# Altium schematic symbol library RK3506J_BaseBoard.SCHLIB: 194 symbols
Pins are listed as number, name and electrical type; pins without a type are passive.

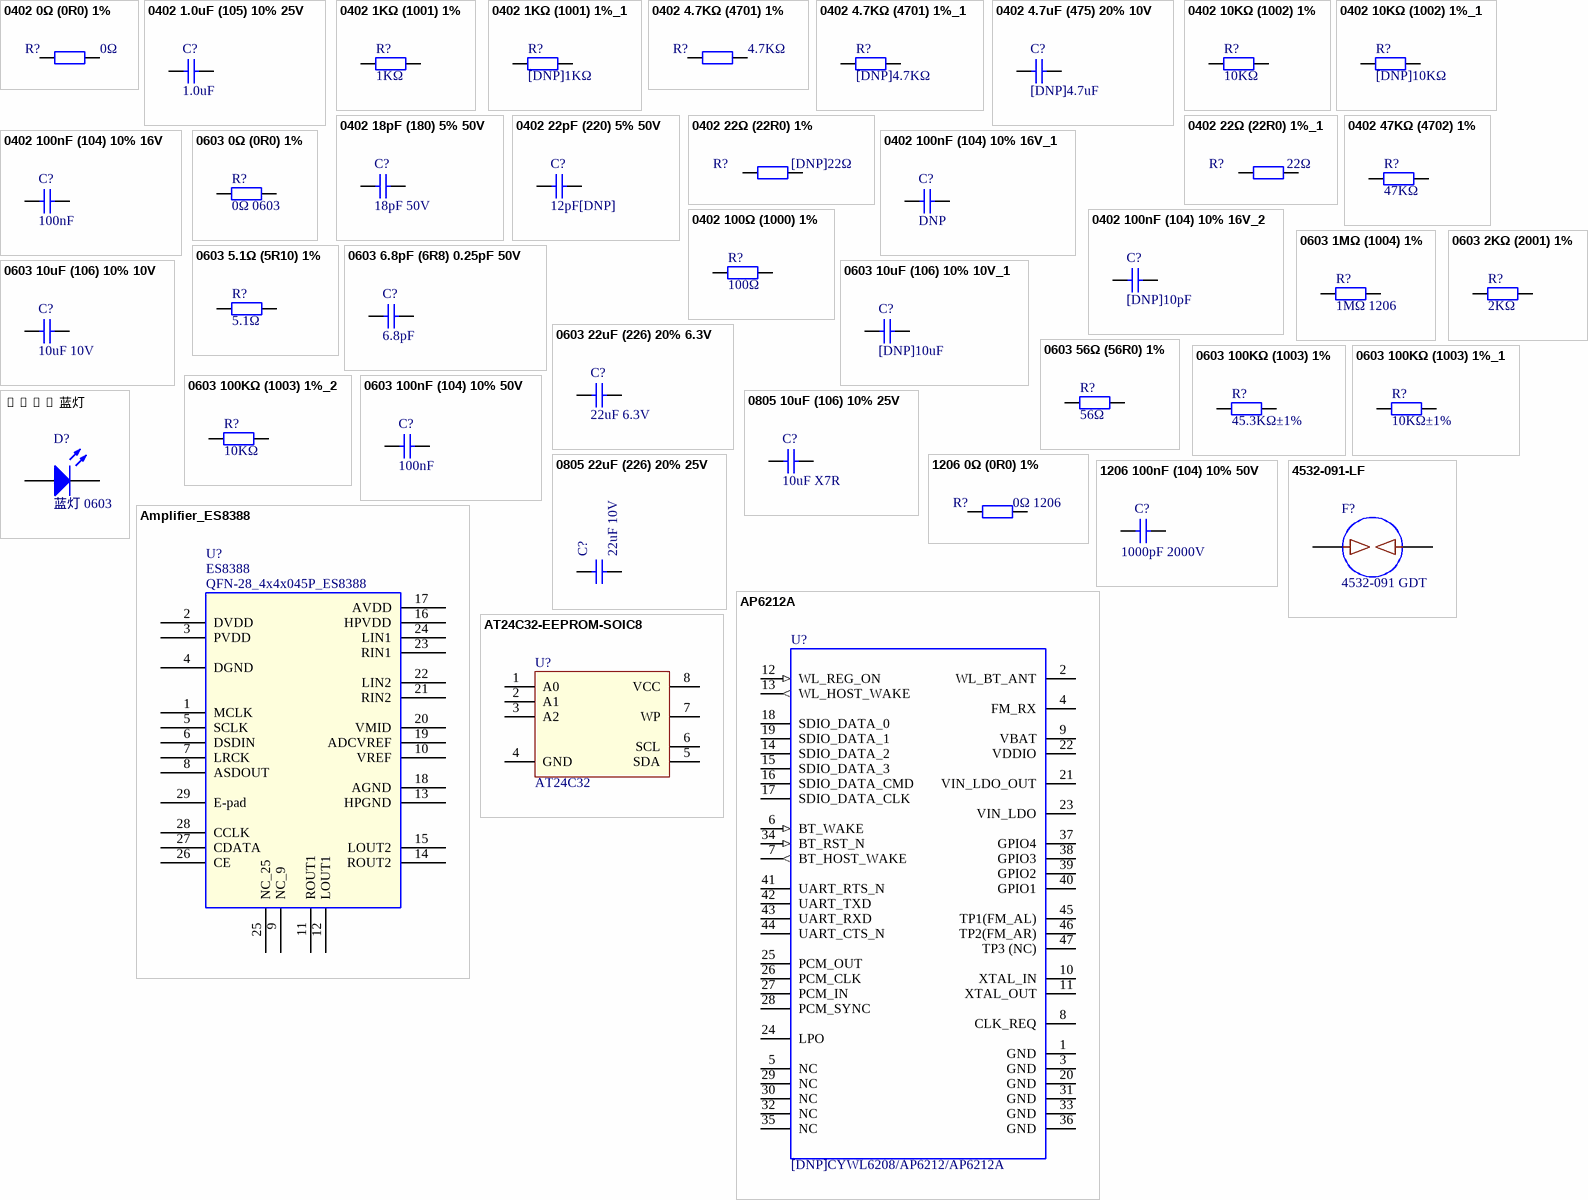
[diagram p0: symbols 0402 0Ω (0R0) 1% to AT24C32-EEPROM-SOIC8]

## 0402 0Ω (0R0) 1%
designator R?, comment 0Ω
贴片电阻
footprint 0402_R
pins: 1, 2

## 0402 1.0uF (105) 10% 25V
designator C?, comment 1.0uF
贴片电容
footprint 0402_C
pins: 1, 2

## 0402 1KΩ (1001) 1%
designator R?, comment 1KΩ
贴片电阻
footprint 0402_R
pins: 1, 2

## 0402 1KΩ (1001) 1%_1
designator R?, comment [DNP]1KΩ
贴片电阻
footprint 0402_R
pins: 1, 2

## 0402 4.7KΩ (4701) 1%
designator R?, comment 4.7KΩ
贴片电阻
footprint 0402_R
pins: 1, 2

## 0402 4.7KΩ (4701) 1%_1
designator R?, comment [DNP]4.7KΩ
贴片电阻
footprint 0402_R
pins: 1, 2

## 0402 4.7uF (475) 20% 10V
designator C?, comment [DNP]4.7uF
贴片电容
footprint 0402_C
pins: 1, 2

## 0402 10KΩ (1002) 1%
designator R?, comment 10KΩ
贴片电阻
footprint 0402_R
pins: 1, 2

## 0402 10KΩ (1002) 1%_1
designator R?, comment [DNP]10KΩ
贴片电阻
footprint 0402_R
pins: 1, 2

## 0402 18pF (180) 5% 50V
designator C?, comment 18pF 50V
贴片电容
footprint 0402_C
pins: 1, 2

## 0402 22pF (220) 5% 50V
designator C?, comment 12pF[DNP]
贴片电容
footprint 0402_C
pins: 1, 2

## 0402 22Ω (22R0) 1%
designator R?, comment [DNP]22Ω
贴片电阻
footprint SOLDER-BRIDGE_R0402-0R
pins: 1, 2

## 0402 22Ω (22R0) 1%_1
designator R?, comment 22Ω
贴片电阻
footprint SOLDER-BRIDGE_R0402-0R
pins: 1, 2

## 0402 47KΩ (4702) 1%
designator R?, comment 47KΩ
贴片电阻
footprint 0402_R
pins: 1, 2

## 0402 100nF (104) 10% 16V
designator C?, comment 100nF
贴片电容
footprint 0402_C
pins: 1, 2

## 0402 100nF (104) 10% 16V_1
designator C?, comment DNP
贴片电容
footprint 0402_C
pins: 1, 2

## 0402 100nF (104) 10% 16V_2
designator C?, comment [DNP]10pF
贴片电容
footprint 0402_C
pins: 1, 2

## 0402 100Ω (1000) 1%
designator R?, comment 100Ω
贴片电阻
footprint 0402_R
pins: 1, 2

## 0603 0Ω (0R0) 1%
designator R?, comment 0Ω 0603
贴片电阻
footprint SOLDER-BRIDGE_R0603-0R
pins: 1, 2

## 0603 1MΩ (1004) 1%
designator R?, comment 1MΩ 1206
贴片电阻
footprint 1206_R
pins: 1, 2

## 0603 2KΩ (2001) 1%
designator R?, comment 2KΩ
贴片电阻
footprint 0603_R
pins: 1, 2

## 0603 5.1Ω (5R10) 1%
designator R?, comment 5.1Ω
贴片电阻
footprint 0603_R
pins: 1, 2

## 0603 6.8pF (6R8) 0.25pF 50V
designator C?, comment 6.8pF
贴片电容
footprint 0603_C
pins: 1, 2

## 0603 10uF (106) 10% 10V
designator C?, comment 10uF 10V
贴片电容
footprint 0603_C
pins: 1, 2

## 0603 10uF (106) 10% 10V_1
designator C?, comment [DNP]10uF
贴片电容
footprint 0402_C
pins: 1, 2

## 0603 22uF (226) 20% 6.3V
designator C?, comment 22uF 6.3V
贴片电容
footprint 0603_C
pins: 1, 2

## 0603 56Ω (56R0) 1%
designator R?, comment 56Ω
贴片电阻
footprint 0603_R
pins: 1, 2

## 0603 100KΩ (1003) 1%
designator R?, comment 45.3KΩ±1%
贴片电阻
footprint 0603_R
pins: 1, 2

## 0603 100KΩ (1003) 1%_1
designator R?, comment 10KΩ±1%
贴片电阻
footprint 0603_R
pins: 1, 2

## 0603 100KΩ (1003) 1%_2
designator R?, comment 10KΩ
贴片电阻
footprint 0603_R
pins: 1, 2

## 0603 100nF (104) 10% 50V
designator C?, comment 100nF
贴片电容
footprint 0603_C
pins: 1, 2

## 0603 蓝灯
designator D?, comment 蓝灯 0603
发光二极管
footprint 0603_LED_S1
pins: A, K

## 0805 10uF (106) 10% 25V
designator C?, comment 10uF X7R
贴片电容
footprint 0805_C
pins: 1, 2

## 0805 22uF (226) 20% 25V
designator C?, comment 22uF 10V
贴片电容
footprint 0805_C
pins: 1, 2

## 1206 0Ω (0R0) 1%
designator R?, comment 0Ω 1206
贴片电阻
footprint 1206_R
pins: 1, 2

## 1206 100nF (104) 10% 50V
designator C?, comment 1000pF 2000V
贴片电容
footprint 1206_C
pins: 1, 2

## 4532-091-LF
designator F?, comment 4532-091 GDT
90V GDT, 1 pole
footprint D1812-BI
pins: 1, 2

## Amplifier_ES8388
designator U?, comment ES8388  PCB Footprint: QFN-28_4x4x045P_ES8388
ES8388 is a high performance, low power and low cost audio CODEC. It consists of 2-ch ADC, 2-ch DAC, microphone amplifier, headphone amplifier, digital sound effects, and analog mixing and gain functions.; Manufacturer: Everest（顺芯）
footprint QFN-28_4x4x045P_ES8388
pins: 1 MCLK, 2 DVDD, 3 PVDD, 4 DGND, 5 SCLK, 6 DSDIN, 7 LRCK, 8 ASDOUT, 9 NC_9, 10 VREF, 11 ROUT1, 12 LOUT1, 13 HPGND (power), 14 ROUT2, 15 LOUT2, 16 HPVDD, 17 AVDD, 18 AGND (power), 19 ADCVREF, 20 VMID, 21 RIN2, 22 LIN2, 23 RIN1, 24 LIN1, 25 NC_25, 26 CE, 27 CDATA, 28 CCLK, 29 E-pad

## AP6212A
designator U?, comment [DNP]CYWL6208/AP6212/AP6212A
footprint LGA44 (AP6212)
pins: 1 GND, 2 WL_BT_ANT, 3 GND, 4 FM_RX, 5 NC, 6 BT_WAKE (in), 7 BT_HOST_WAKE (out), 8 CLK_REQ, 9 VBAT, 10 XTAL_IN, 11 XTAL_OUT, 12 WL_REG_ON (in), 13 WL_HOST_WAKE (out), 14 SDIO_DATA_2, 15 SDIO_DATA_3, 16 SDIO_DATA_CMD, 17 SDIO_DATA_CLK, 18 SDIO_DATA_0, 19 SDIO_DATA_1, 20 GND, 21 VIN_LDO_OUT, 22 VDDIO, 23 VIN_LDO, 24 LPO, 25 PCM_OUT, 26 PCM_CLK, 27 PCM_IN, 28 PCM_SYNC, 29 NC, 30 NC, 31 GND, 32 NC, 33 GND, 34 BT_RST_N (in), 35 NC, 36 GND, 37 GPIO4, 38 GPIO3, 39 GPIO2, 40 GPIO1, 41 UART_RTS_N, 42 UART_TXD, 43 UART_RXD, 44 UART_CTS_N, 45 TP1(FM_AL), 46 TP2(FM_AR), 47 TP3 (NC)

## AT24C32-EEPROM-SOIC8
designator U?, comment AT24C32
AT24C32 EEPROM
footprint SOIC-8_150mil
pins: 1 A0, 2 A1, 3 A2, 4 GND, 5 SDA, 6 SCL, 7 WP, 8 VCC

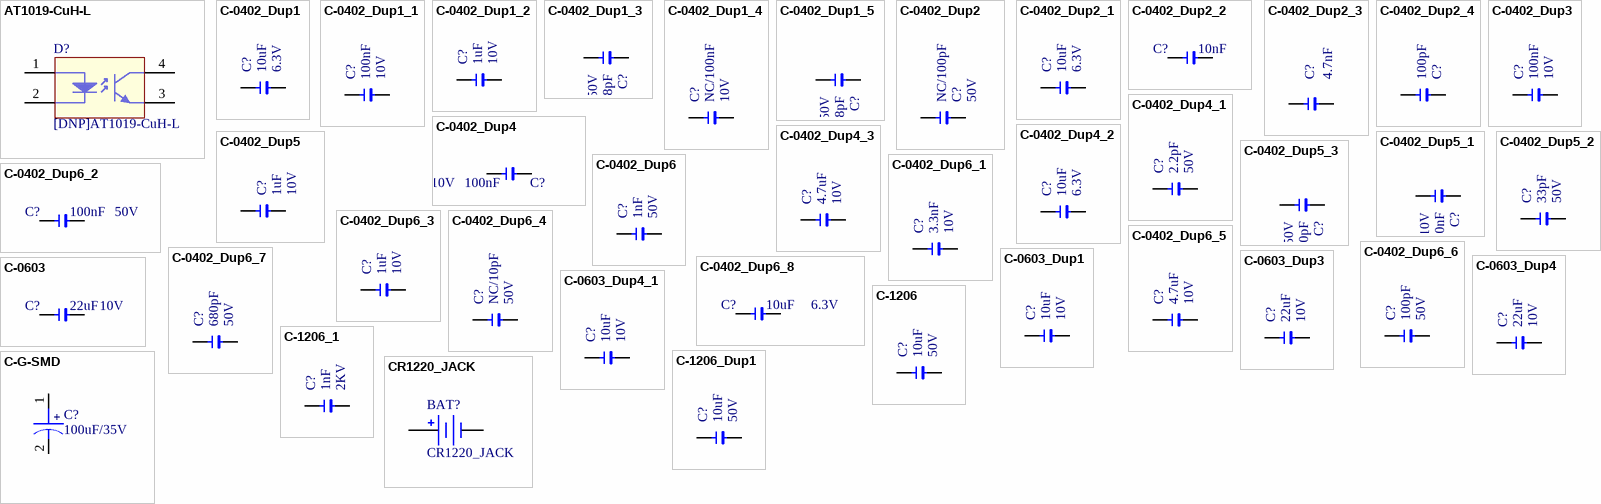
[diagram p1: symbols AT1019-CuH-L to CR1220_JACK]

## AT1019-CuH-L
designator D?, comment [DNP]AT1019-CuH-L
Photo Transistor，AT101X是一款由一个GaAs发光二极管和一个NPN光电晶体管组成的光电耦合器
footprint SOP4-300mil
pins: 1 A, 2 C, 3 E, 4 C

## C-0402_Dup1
designator C?, comment 10uF  DSC2: 6.3V
Part Number: C020102120068; Part Name: 贴片电容; PCB Footprint: C0402; DSC1: ±20%; DSC3: X5R; ID: 68
footprint C0402
pins: 1, 2

## C-0402_Dup1_1
designator C?, comment 100nF  DSC2: 10V
Part Number: C020102120060; Part Name: 贴片电容; PCB Footprint: C0402; ERP Number: 1010010034; DSC1: ±10%; DSC3: X7R; ID: 60
footprint C0402
pins: 1, 2

## C-0402_Dup1_2
designator C?, comment 1uF  DSC2: 10V
Part Name: 贴片电容; Part Number: C020102120064; PCB Footprint: C0402; ID: 64; DSC3: X5R; DSC1: ±10%; ERP Number: 1010010006
footprint C0402
pins: 1, 2

## C-0402_Dup1_3
designator C?, comment 18pF  DSC2: 50V
Part Number: C020102120027; Part Name: 贴片电容; PCB Footprint: C0402; ERP Number: 1010010007; DSC1: ±5%; DSC3: C0G; ID: 27
footprint C0402
pins: 1, 2

## C-0402_Dup1_4
designator C?, comment NC/100nF  DSC2: 10V
Part Number: C020102120060; Part Name: 贴片电容; ERP Number: 1010010034; DSC1: ±10%; DSC3: X7R; ID: 60; PCB Footprint: C0402
footprint C0402
pins: 1, 2

## C-0402_Dup1_5
designator C?, comment NC/18pF  DSC2: 50V
Part Number: C020102120027; Part Name: 贴片电容; PCB Footprint: C0402; ERP Number: 1010010007; DSC1: ±5%; DSC3: C0G; ID: 27
footprint C0402
pins: 1, 2

## C-0402_Dup2
designator C?, comment NC/100pF  DSC2: 50V
Part Number: C020102120040; Part Name: 贴片电容; ERP Number: 1010010013; DSC1: ±5%; DSC3: C0G; ID: 40; PCB Footprint: C0402
footprint C0402
pins: 1, 2

## C-0402_Dup2_1
designator C?, comment 10uF  DSC2: 6.3V
Part Name: 贴片电容; Part Number: C020102120068; PCB Footprint: C0402; ID: 68; DSC3: X5R; DSC1: ±20%
footprint C0402
pins: 1, 2

## C-0402_Dup2_2
designator C?, comment 10nF
Part Number: C020102120057; Part Name: 贴片电容; ERP Number: 1010010015; DSC1: ±10%; DSC2: 50V; DSC3: X7R; ID: 57; PCB Footprint: C0402
footprint C0402
pins: 1, 2

## C-0402_Dup2_3
designator C?, comment 4.7nF
Part Name: 贴片电容; Part Number: C020102120056; ID: 56; DSC3: X7R; DSC2: 50V; DSC1: ±10%; ERP Number: 1010010041; PCB Footprint: C0402
footprint C0402
pins: 1, 2

## C-0402_Dup2_4
designator C?, comment 100pF
Part Number: C020102120040; Part Name: 贴片电容; ERP Number: 1010010013; DSC1: ±5%; DSC2: 50V; DSC3: C0G; ID: 40; PCB Footprint: C0402
footprint C0402
pins: 1, 2

## C-0402_Dup3
designator C?, comment 100nF  DSC2: 10V
Manufacture: 三星¦国巨¦村田; Part Name: 贴片电容; Part Number: C020102120060; PCB Footprint: C0402; ID: 60; DSC3: X7R; DSC1: ±10%
footprint 1206
footprint C0402
pins: 1, 2

## C-0402_Dup4
designator C?, comment 100nF  DSC2: 10V
Manufacture: 三星¦国巨¦村田; Part Name: 贴片电容; Part Number: C020102120061; PCB Footprint: C0402; ID: 61; DSC3: X7R; DSC1: ±10%; ERP Number: 1010200128
footprint 1206
footprint C0402
pins: 1, 2

## C-0402_Dup4_1
designator C?, comment 2.2pF  DSC2: 50V
Part Number: C020102120013; Part Name: 贴片电容; Manufacture: 三星¦国巨¦村田; PCB Footprint: C0402; ERP Number: 1010200109; DSC1: ±0.1PF; DSC3: C0G; ID: 13
footprint 1206
footprint C0402
pins: 1, 2

## C-0402_Dup4_2
designator C?, comment 10uF  DSC2: 6.3V
Part Number: C020102120068; Part Name: 贴片电容; Manufacture: 三星¦国巨¦村田; PCB Footprint: C0402; DSC1: ±20%; DSC3: X5R; ID: 68
footprint 1206
footprint C0402
pins: 1, 2

## C-0402_Dup4_3
designator C?, comment 4.7uF  DSC2: 10V
Part Number: C020102120067; Part Name: 贴片电容; Manufacture: 三星¦国巨¦村田; PCB Footprint: C0402; DSC1: ±20%; DSC3: X5R; ID: 67
footprint 1206
footprint C0402
pins: 1, 2

## C-0402_Dup5
designator C?, comment 1uF  DSC2: 10V
Part Number: C020102120064; Part Name: 贴片电容; Manufacture: 三星¦国巨¦村田; ERP Number: 1010200054; DSC1: ±10%; DSC3: X5R; ID: 64; PCB Footprint: C0402
footprint 1206
footprint C0402
pins: 1, 2

## C-0402_Dup5_1
designator C?, comment 100nF  DSC2: 10V
Part Number: C020102120060; Part Name: 贴片电容; Manufacture: 三星¦国巨¦村田; DSC1: ±10%; DSC3: X7R; ID: 60; PCB Footprint: C0402
footprint 1206
footprint C0402
pins: 1, 2

## C-0402_Dup5_2
designator C?, comment 33pF  DSC2: 50V
Manufacture: 三星¦国巨¦村田; Part Name: 贴片电容; Part Number: C020102120033; ID: 33; DSC3: C0G; DSC1: ±5%; ERP Number: 1010200087; PCB Footprint: C0402
footprint 1206
footprint C0402
pins: 1, 2

## C-0402_Dup5_3
designator C?, comment 100pF  DSC2: 50V
Manufacture: 三星¦国巨¦村田; Part Name: 贴片电容; Part Number: C020102120040; ID: 40; DSC3: C0G; DSC1: ±5%; ERP Number: 1010200152; PCB Footprint: C0402
footprint 1206
footprint C0402
pins: 1, 2

## C-0402_Dup6
designator C?, comment 1nF  DSC2: 50V
Part Number: C020102120054; Part Name: 贴片电容; ERP Number: 1010010021; DSC1: ±10%; DSC3: X7R; ID: 54; PCB Footprint: C0402
footprint C0402
pins: 1, 2

## C-0402_Dup6_1
designator C?, comment 3.3nF  DSC2: 10V
Part Number: C020102120064; Part Name: 贴片电容; ERP Number: 1010010006; DSC1: ±10%; DSC3: X5R; ID: 64; PCB Footprint: C0402
footprint C0402
pins: 1, 2

## C-0402_Dup6_2
designator C?, comment 100nF  DSC2: 50V
Part Name: 贴片电容; Part Number: C020102120061; ID: 61; DSC3: X7R; DSC1: ±10%; PCB Footprint: C0402
footprint C0402
pins: 1, 2

## C-0402_Dup6_3
designator C?, comment 1uF  DSC2: 10V
Part Number: C020102120064; Part Name: 贴片电容; ERP Number: 1010010006; DSC1: ±10%; DSC3: X5R; ID: 64; PCB Footprint: C0402
footprint C0402
pins: 1, 2

## C-0402_Dup6_4
designator C?, comment NC/10pF  DSC2: 50V
Part Number: C020102120021; Part Name: 贴片电容; ERP Number: 1010010024; DSC1: ±5%; DSC3: C0G; ID: 21; PCB Footprint: C0402
footprint C0402
pins: 1, 2

## C-0402_Dup6_5
designator C?, comment 4.7uF  DSC2: 10V
Part Name: 贴片电容; Part Number: C020102120067; PCB Footprint: C0402; ID: 67; DSC3: X5R; DSC1: ±10%; ERP Number: 1010010043
footprint C0402
pins: 1, 2

## C-0402_Dup6_6
designator C?, comment 100pF  DSC2: 50V
Part Name: 贴片电容; Part Number: C020102120040; ID: 40; DSC3: C0G; DSC1: ±5%; ERP Number: 1010010013; PCB Footprint: C0402
footprint C0402
pins: 1, 2

## C-0402_Dup6_7
designator C?, comment 680pF  DSC2: 50V
Part Name: 贴片电容; Part Number: C020102120052; ID: 52; DSC3: C0G; DSC1: ±5%; ERP Number: 1010010039; PCB Footprint: C0402
footprint C0402
pins: 1, 2

## C-0402_Dup6_8
designator C?, comment 10uF  DSC2: 6.3V
Part Name: 贴片电容; Part Number: C020102120068; PCB Footprint: C0402; ID: 68; DSC3: X5R; DSC1: ±20%
footprint C0402
pins: 1, 2

## C-0603
designator C?, comment 22uF  DSC2: 10V
Part Name: 贴片电容; PCB Footprint: C0603; DSC1: ±20%; DSC3: X5R; ID: 89
footprint C0603
pins: 1, 2

## C-0603_Dup1
designator C?, comment 10uF  DSC2: 10V
Part Name: 贴片电容; Part Number: C020102120071; PCB Footprint: C0603; ID: 71; DSC3: X5R; DSC1: ±20%
footprint C0603
pins: 1, 2

## C-0603_Dup3
designator C?, comment 22uF  DSC2: 10V
Part Number: C020107143899; Part Name: 贴片电容; Manufacture: 三星¦国巨¦村田; PCB Footprint: C0603; DSC1: ±20%; DSC3: X5R; ID: 83
footprint 1206
footprint C0603
pins: 1, 2

## C-0603_Dup4
designator C?, comment 22uF  DSC2: 10V
Part Name: 贴片电容; ID: 89; DSC3: X5R; DSC1: ±20%; PCB Footprint: C0603
footprint C0603
pins: 1, 2

## C-0603_Dup4_1
designator C?, comment 10uF  DSC2: 10V
Part Name: 贴片电容; Part Number: C020102120071; ID: 71; DSC3: X5R; DSC1: ±20%; PCB Footprint: C0603
footprint C0603
pins: 1, 2

## C-1206
designator C?, comment 10uF  DSC2: 50V
Part Number: C020103263826; Part Name: 贴片电容; Manufacture: 三星¦国巨¦村田; DSC1: ±10%; DSC3: X5R; ID: 79; PCB Footprint: C1206
footprint 1206
footprint C1206
pins: 1, 2

## C-1206_1
designator C?, comment 1nF  DSC2: 2KV
Manufacture: 三星¦国巨¦村田; Part Name: 贴片电容; Part Number: C020102120077; PCB Footprint: C1206; ID: 77; DSC3: X7R; DSC1: ±10%; ERP Number: 1010200094
footprint 1206
footprint C1206
pins: 1, 2

## C-1206_Dup1
designator C?, comment 10uF  DSC2: 50V
Part Number: C020103263826; Part Name: 贴片电容; DSC1: ±10%; DSC3: X5R; ID: 79; PCB Footprint: C1206
footprint C1206
pins: 1, 2

## C-G-SMD
designator C?, comment 100uF/35V
Manufacture: 艾华; Part Name: 固态电容; ID: 13; DSC8: 贴片; DSC7: SVZ1VM101E09E00RAXXX(艾华); DSC6: 6.3x9mm; DSC5: -55~105℃; DSC4: 2000H; DSC3: 40mΩ; DSC2: 35V; DSC1: ±20%; PCB Footprint: CAPAE660X900
footprint CAPAE660X900
pins: 1, 2

## CR1220_JACK
designator BAT?
footprint BAT-SMD_CR1220-2ZX
pins: 1, 2

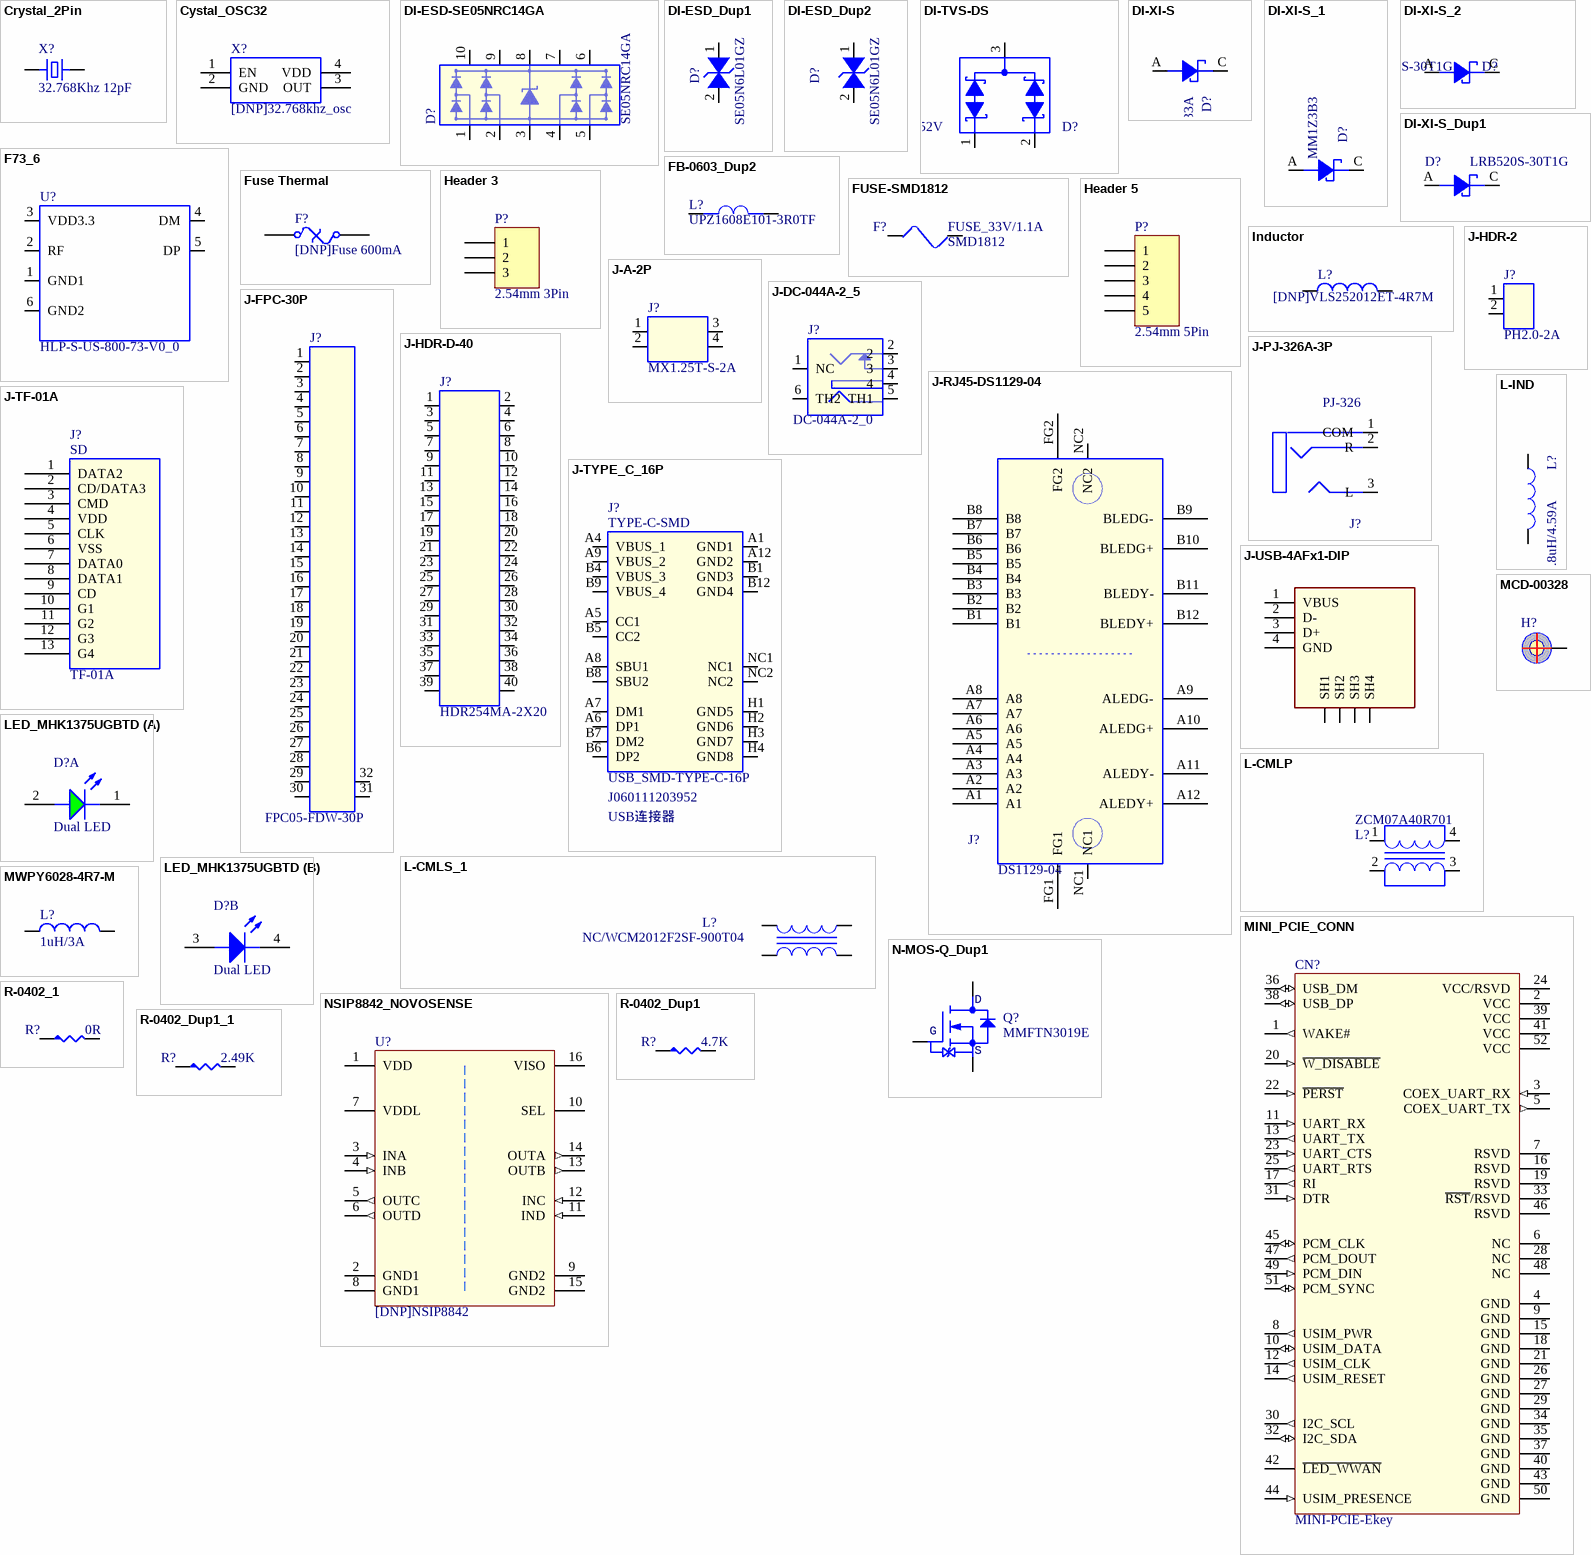
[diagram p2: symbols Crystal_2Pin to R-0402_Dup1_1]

## Crystal_2Pin
designator X?, comment 32.768Khz 12pF
无源2脚晶振
footprint SMD-3215-2P
pins: 1, 2

## Cystal_OSC32
designator X?, comment [DNP]32.768khz_osc
footprint SMD_2520
pins: 1 EN, 2 GND, 3 OUT, 4 VDD

## DI-ESD-SE05NRC14GA
designator D?, comment SE05NRC14GA
Manufacture: SOCAY(硕凯); Part Number: C040504013981; Part Name: ESD; PCB Footprint: DFN2510-10L; Solder: 推荐; ID: 8; DSC5: Cj=0.4pF; DSC4: Vc=20V; DSC3: Vbr=8V; DSC2: Vdc=5V; DSC1: 双向; ERP Number: 1010060056
footprint DFN2510-10L
pins: 1, 2, 3, 4, 5, 6, 7, 8, 9, 10

## DI-ESD_Dup1
designator D?, comment SE05N6L01GZ
ESD 0402; Manufacturer: INPAQ; Manufacture P/N: MLVG04021R0UV18; Part Number: C040505124710; Manufacture: SOCAY(硕凯); PN Type: Varistor; ERP Number: 1010060072; DSC1: 双向; DSC2: Vdc=5V; DSC4: Vc=11V; DSC5: Cj=0.5pF; ID: 9; Solder: 推荐
footprint ESD0402
pins: 1 I/O2, 2 I/O1

## DI-ESD_Dup2
designator D?, comment SE05N6L01GZ
ESD 0402; Manufacturer: INPAQ; Manufacture P/N: MLVG04021R0UV18; Part Number: C040505124710; Manufacture: SOCAY(硕凯); PN Type: Varistor; ERP Number: 1010060072; DSC1: 双向; DSC2: Vdc=5V; DSC4: Vc=11V; DSC5: Cj=0.5pF; ID: 9; Solder: 推荐
footprint ESD0402
pins: 1 I/O2, 2 I/O1

## DI-TVS-DS
designator D?, comment BST23C152V
Part Number: C040602260017; Part Name: TVS; Manufacture: BORN(伯恩半导体); ERP Number: 1010060013; DSC1: 双向; DSC2: Vrwm=15V; DSC3: VBR=16.7V; DSC4: Vc=30V; DSC5: Ipp=10A; DSC6: Ppp=250W; DSC7: Cj=100pF; ID: 17; Solder: 推荐; PCB Footprint: SOT23
footprint SOT23
pins: 1, 2, 3

## DI-XI-S
designator D?, comment SMBJ33A
Manufacture: SOCAY(硕凯); Part Name: TVS; CLASS: IC; ID: 33; DSC6: Ppp=600W; DSC5: Ipp=11.26A; DSC4: Vc=53.3V; DSC3: VBR=36.7V; DSC2: Vrwm=33V; DSC1: 单向; PCB Footprint: SMB_DO-214AA
footprint SMB_DO-214AA
pins: A, C

## DI-XI-S_1
designator D?, comment MM1Z3B3
高精度（2%）3.3V稳压管，MM1Z3V3; Manufacture: SOCAY(硕凯); Part Name: TVS; CLASS: IC; ID: 33; DSC6: Ppp=600W; DSC5: Ipp=11.26A; DSC4: Vc=53.3V; DSC3: VBR=36.7V; DSC2: Vrwm=33V; DSC1: 单向; PCB Footprint: SMB_DO-214AA
footprint SOD123
pins: A, C

## DI-XI-S_2
designator D?, comment LRB520S-30T1G
Part Number: C040202220002; Part Name: 肖特基二级管; Manufacture: LRC(乐山无线电); CLASS: IC; PCB Footprint: SOD523; ERP Number: 1010060005; DSC1: VR=30V; DSC2: IF=200mA; DSC3: VF=350mV/10mA; DSC4: IR=0.5uA; ID: 2; Solder: 推荐
footprint SOD523
pins: A, C

## DI-XI-S_Dup1
designator D?, comment LRB520S-30T1G
Part Number: C040202220002; Part Name: 肖特基二级管; Manufacture: 乐山无线电; CLASS: IC; PCB Footprint: SOD523; DSC1: VR=30V; DSC2: IF=200mA; DSC3: VF=350mV/10mA; DSC4: IR=0.5uA; ID: 2; Solder: 推荐
footprint SOD523
pins: A, C

## F73_6
designator U?, comment HLP-S-US-800-73-V0_0
PCB Footprint: WIFI-U_12_2x13_f73
footprint WIFI-U_12_2x13_f73
pins: 1 GND1, 2 RF, 3 VDD3.3, 4 DM, 5 DP, 6 GND2

## FB-0603_Dup2
designator L?, comment UPZ1608E101-3R0TF
SMD Multilayer Ferrite Chip Bead,3A,30Ohm,0.03R; Manufacturer: SUNLORD; Manufacture2 P/N: PBY160808T-400Y-N; Manufacture P/N: PZ1608D300-3R0TF; Part Number: C060502370005; Manufacture: Sunlord(顺络); Part Name: 贴片磁珠; PN Type: SMD FERRITE BEAD; ID: 5; DSC4: 电源线; DSC3: DCR=30mΩ; DSC1: 100Ω@100MHz; ERP Number: 1010030006; PCB Footprint: L0603
footprint L0603
pins: 1, 2

## Fuse Thermal
designator F?, comment [DNP]Fuse 600mA
Thermal Fuse
footprint 0805_R
pins: 1, 2

## FUSE-SMD1812
designator F?, comment FUSE_33V/1.1A  PCB: SMD1812
Part Name: 自恢复保险丝; Manufacture: SOCAY(硕凯); ERP Number: 1010050020; DSC1: Vdc=33V; DSC2: Ihold=1.1A; DSC3: SCF110-33-1812RB; ID: 21
footprint SMD1812
pins: 1, 2

## Header 3
designator P?, comment 2.54mm 3Pin
Header, 3-Pin
footprint HDR1X3 (Connector; Header; 3 Position)
signal-integrity model Connector
pins: 1, 2, 3

## Header 5
designator P?, comment 2.54mm 5Pin
Header, 5-Pin
footprint HDR1X5 (Connector; Header; 5 Position)
signal-integrity model Connector
pins: 1, 2, 3, 4, 5

## Inductor
designator L?, comment [DNP]VLS252012ET-4R7M
Inductor; Code_IEC: 1005; Value: 4.7uH
simulation model INDUCTOR (Inductor)
signal-integrity model Inductor
footprint VLS252012
pins: 1, 2

## J-A-2P
designator J?, comment MX1.25T-S-2A
Part Number: J020102800058; ID: 6; DSC6: X9821WVS-02-9TSN(星坤); DSC5: 推荐型号：JLX-1.25T-2AB(九龙熹); DSC4: 米黄色胶壳 耐高温; DSC3: 立贴; DSC2: 1.25mm间距; DSC1: 2p; ERP Number: 1030020014; PCB Footprint: MX125T-S-2A
footprint MX125T-S-2A
pins: 1, 2, 3, 4

## J-DC-044A-2_5
designator J?, comment DC-044A-2_0
Part Number: J100103010003; Part Name: DC座; DSC1: 通孔弯针，内径2mm，2.5A，24VDC; DSC2: 11.5*10.1*7.3mm; DSC3: 通孔弯针; DSC4: DC-044A-2.5A-2.0(星坤); DSC5: DC0044A（九龙熹）; ID: 3; PCB Footprint: DC-044A-2_0-DIP
footprint DC-044A-2_0-DIP
pins: 1 NC, 2, 3, 4, 5 TH1, 6 TH2

## J-FPC-30P
designator J?, comment FPC05-FDW-30P
Part Name: FPC座; Part Number: J030102870078; PCB Footprint: FPC05-30P; ID: 19; DSC6: X05A20L30T(星坤); DSC5: 镀锡; DSC4: H=2mm; DSC3: 下接 翻盖 卧贴; DSC2: 0.5mm间距; DSC1: 30P; ERP Number: 1030030008
footprint FPC05-30P
pins: 1, 2, 3, 4, 5, 6, 7, 8, 9, 10, 11, 12, 13, 14, 15, 16, 17, 18, 19, 20, 21, 22, 23, 24, 25, 26, 27, 28, 29, 30, 31, 32

## J-HDR-2
designator J?, comment PH2.0-2A
Part Name: PH; ID: 78; DSC5: 推荐型号：A2001WV-2P-1-RD(CJT); DSC4: 红色胶壳 耐高温; DSC3: 通孔180度直针; DSC2: 2.0mm间距; DSC1: 2p; ERP Number: 1030020066; PCB Footprint: PH200-2A
footprint PH200-2A
pins: 1, 2

## J-HDR-D-40
designator J?, comment HDR254MA-2X20
Part Number: J010104013835; Part Name: 双排针; ERP Number: 1030010029; DSC1: 双排单塑; DSC2: 2x20; DSC3: 2.54mm脚距; DSC4: 通孔直针; DSC5: 针长11.5mm 3+2.5(H塑高)+6mm; DSC6: 黑胶 PA9T; DSC7: 推荐型号：A2541WV-2x20P(CJT); ID: 64
footprint HDR254MA-2X20
pins: 1, 2, 3, 4, 5, 6, 7, 8, 9, 10, 11, 12, 13, 14, 15, 16, 17, 18, 19, 20, 21, 22, 23, 24, 25, 26, 27, 28, 29, 30, 31, 32, 33, 34, 35, 36, 37, 38, 39, 40

## J-PJ-326A-3P
designator J?, comment PJ-326
Part Name: 音频耳机座; Part Number: J050502940003; P/N: 182K00300S; PCB Footprint: PJ-326A-3P; DSC4: PJ-326(星坤); DSC2: 14*5.6*5.1mm; DSC1: 3.5mm贴片式耳机座 凸头 3P 双定位柱; ERP Number: 1030130016
footprint PJ-326A-3P
pins: 1 COM, 2 R, 3 L

## J-RJ45-DS1129-04
designator J?, comment DS1129-04
Part Name: RJ45; Part Number: J120103060002; PCB Footprint: RJ45-TH_DS1129-04; ID: 2; DSC5: DS1129-04-S8B0P-X(CONNFLY); DSC4: HQST-E-125JAO1A-YG(盈盛电子); DSC3: -40℃~+85℃; DSC2: 通孔弯针; DSC1: RJ45 8P8C,1*2,LED左黄右绿,全包无弹片，上开口，半金锡,黑色,32.26x15.75x13.2mm; ERP Number: 1030110003
footprint RJ45-TH_DS1129-04
pins: A1, A2, A3, A4, A5, A6, A7, A8, A9 ALEDG-, A10 ALEDG+, A11 ALEDY-, A12 ALEDY+, B1, B2, B3, B4, B5, B6, B7, B8, B9 BLEDG-, B10 BLEDG+, B11 BLEDY-, B12 BLEDY+, FG1, FG2, NC1, NC2

## J-TF-01A
designator J?, comment SD  PCB Footprint: TF-01A
Part Name: SD卡座; Part Number: J080102980002; ID: 2; DSC4: TF-01A(韩荣); DSC3: 贴片; DSC1: TF卡座 自弹式
footprint TF-01A
pins: 1 DATA2, 2 CD/DATA3, 3 CMD, 4 VDD, 5 CLK, 6 VSS, 7 DATA0, 8 DATA1, 9 CD, 10 G1, 11 G2, 12 G3, 13 G4

## J-TYPE_C_16P
designator J?, comment TYPE-C-SMD  PCB Footprint: USB_SMD-TYPE-C-16P  Part Name: USB连接器  Part Number: J060111203952
ID: 11; DSC5: TYPE-CF-16P-RAT-L7.3（九龙熹）; DSC4: U262-161N-4BVC11（星坤）; DSC3: 卧贴; DSC2: 8.6*2.5mm; DSC1: TYPE-C，16Pin母座，卧贴，无卷边，耐高温
footprint USB_SMD-TYPE-C-16P
pins: A1 GND1, A4 VBUS_1, A5 CC1, A6 DP1, A7 DM1, A8 SBU1, A9 VBUS_2, A12 GND2, B1 GND3, B4 VBUS_3, B5 CC2, B6 DP2, B7 DM2, B8 SBU2, B9 VBUS_4, B12 GND4, H1 GND5, H2 GND6, H3 GND7, H4 GND8, NC1, NC2

## J-USB-4AFx1-DIP
designator CN?  (value not drawn)
USB,TYPE-A,1PORT,SIDE-VERTICAL,SHIELD; VSTNO: H00025
footprint USB-A-TH_USB-226-BRY
pins: 1 VBUS, 2 D-, 3 D+, 4 GND, SH1, SH2, SH3, SH4

## L-CMLP
designator L?, comment ZCM07A40R701
Manufacture: 宗成; Part Name: 电源共模电感; ID: 11; DSC6: SMD_4P,7x6x4 mm; DSC5: -40℃ ~ +85℃; DSC3: 4A; DSC2: 600Ω@100MHz; PCB Footprint: CMLP-ACM7060
footprint CMLP-ACM7060
pins: 1, 2, 3, 4

## L-CMLS_1
designator L?, comment NC/WCM2012F2SF-900T04
Part Name: 信号共模电感; Part Number: C060402360001; Manufacture: TAI-TECH(台庆); ERP Number: 1010030007; DSC1: 90uH@100kHz; DSC2: 90Ω@100MHz; DSC3: 400mA; DSC4: DCR=300mΩ; DSC5: -40℃ ~ +125℃; DSC6: SMD_4P,2x1.2mm; ID: 1; PCB Footprint: CMLS-ACM2012
footprint CMLS-ACM2012
pins: 1, 2, 3, 4

## L-IND
designator L?, comment 7.8uH/4.59A
Manufacture: 长江微电¦爱普微; Part Number: C060202340040; Part Name: 功率电感; ID: 40; DSC8: APH0630T100M(爱普微); DSC7: FXL0630-100-M(长江微电); DSC5: 7.3*6.6*2.8mm; DSC4: Rdc=67mΩ; DSC3: Irms=4.5A; DSC2: Isat=5.5A; DSC1: ±20%; ERP Number: 1010030057; PCB Footprint: IND_706628
footprint IND_706628
pins: 1, 2

## LED_MHK1375UGBTD
designator D?, comment Dual LED
MHK1375UGBTD，Dual LED pack
footprint LED-TH_4P-L12.8-W4.4_C9900044135
part A pins: 1 A1, 2 C1
part B pins: 3 A2, 4 C2

## MCD-00328
designator H?, comment POSITION HOLE  (value not drawn)  (no BOM)
POSITION HOLE C7D3R5; Internal_Part_Number: MCD-00328; Part_Type: Misc; Part_Preference: Recommended; ID: 2950; ShowFields: YES
footprint SMD_NUT_M3x5.56x5mm
pins: 1

## MINI_PCIE_CONN
designator CN?, comment MINI-PCIE-Ekey
mini pcie connector for 4G modem and so on
footprint CONN-SMD_PCIE-52P52H
pins: 1 WAKE# (out), 2 VCC (power), 3 COEX_UART_RX (in), 4 GND (power), 5 COEX_UART_TX (out), 6 NC, 7 RSVD, 8 USIM_PWR (out), 9 GND (power), 10 USIM_DATA (io), 11 UART_RX (in), 12 USIM_CLK (out), 13 UART_TX (out), 14 USIM_RESET (out), 15 GND (power), 16 RSVD, 17 RI (out), 18 GND (power), 19 RSVD, 20 ~{W_DISABLE} (in), 21 GND (power), 22 ~{PERST} (in), 23 UART_CTS (in), 24 VCC/RSVD, 25 UART_RTS (out), 26 GND (power), 27 GND (power), 28 NC, 29 GND (power), 30 I2C_SCL (out), 31 DTR (in), 32 I2C_SDA (io), 33 ~{RST}/RSVD, 34 GND (power), 35 GND (power), 36 USB_DM (io), 37 GND (power), 38 USB_DP (io), 39 VCC (power), 40 GND (power), 41 VCC (power), 42 ~{LED_WWAN} (oc), 43 GND (power), 44 USIM_PRESENCE (in), 45 PCM_CLK (io), 46 RSVD, 47 PCM_DOUT (out), 48 NC, 49 PCM_DIN (in), 50 GND (power), 51 PCM_SYNC (io), 52 VCC (power)

## MWPY6028-4R7-M
designator L?, comment 1uH/3A
Inductor  MWPY6028-4R7-M; Code_IEC: 1005; Value: 10mH
simulation model INDUCTOR (Inductor)
signal-integrity model Inductor
footprint IND-SMD_L4.4-W4.2
pins: 1, 2

## N-MOS-Q_Dup1
designator Q?, comment MMFTN3019E
Part Number: C030202190004; Part Name: N-MOS; Manufacture: ST(先科); PCB Footprint: SOT523; ERP Number: 1010080001; DSC1: Vds=30V; DSC2: Id=100mA; DSC3: Vgs(th)=1.5V; DSC4: Vgs=±20V; DSC5: pd=150mW; ID: 4
footprint SOT523
pins: 1 GATE, 2 SOURCE, 3 DRAIN

## NSIP8842_NOVOSENSE
designator U?, comment [DNP]NSIP8842
NSIP8842 isolation 150Mbps 2IN 2OUT
footprint SOIC-16
pins: 1 VDD (power), 2 GND1 (power), 3 INA (in), 4 INB (in), 5 OUTC (out), 6 OUTD (out), 7 VDDL (power), 8 GND1 (power), 9 GND2 (power), 10 SEL, 11 IND (in), 12 INC (in), 13 OUTB (out), 14 OUTA (out), 15 GND2 (power), 16 VISO (power)

## R-0402_1
designator R?, comment 0R
Part Name: 贴片电阻; Part Number: C011002080413; PCB Footprint: R0402; DSC1: ±1%; DSC2: 1/16W; ID: 413
footprint R0402
pins: 1, 2

## R-0402_Dup1
designator R?, comment 4.7K
Part Name: 贴片电阻; Part Number: C011002080818; PCB Footprint: R0402; ERP Number: 1010020013; DSC1: ±1%; DSC2: 1/16W; ID: 818
footprint R0402
pins: 1, 2

## R-0402_Dup1_1
designator R?, comment 2.49K
Part Name: 贴片电阻; Part Number: C011002080785; PCB Footprint: R0402; ERP Number: 1010020050; DSC1: ±1%; DSC2: 1/16W; ID: 785
footprint R0402
pins: 1, 2

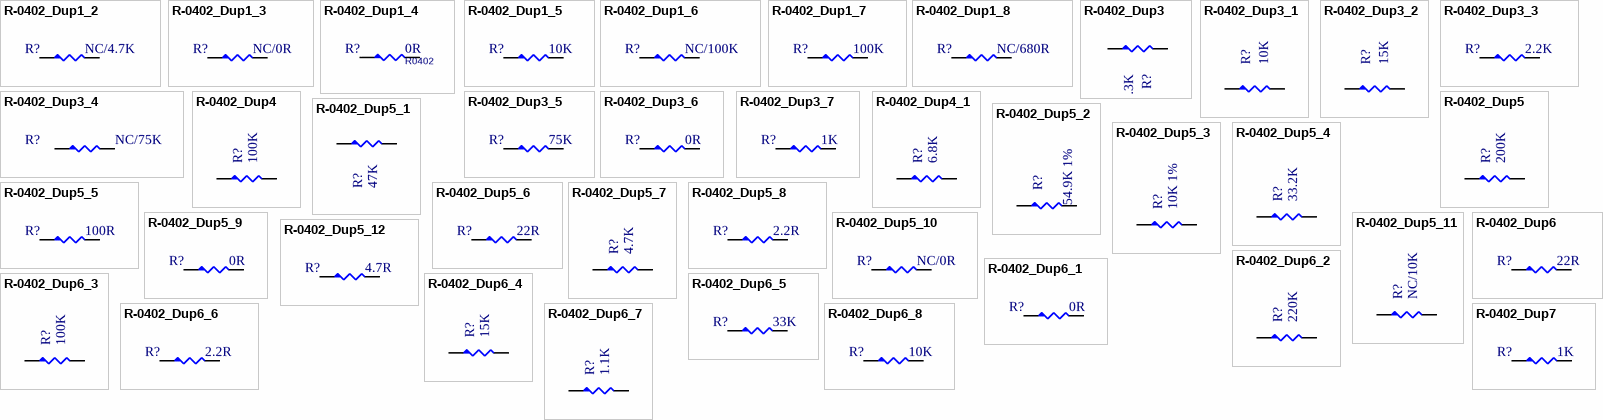
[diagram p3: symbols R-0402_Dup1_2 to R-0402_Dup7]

## R-0402_Dup1_2
designator R?, comment NC/4.7K
Part Number: C011002080818; Part Name: 贴片电阻; PCB Footprint: R0402; ID: 818; DSC2: 1/16W; DSC1: ±1%; ERP Number: 1010020013
footprint R0402
pins: 1, 2

## R-0402_Dup1_3
designator R?, comment NC/0R
Part Number: C011002080413; Part Name: 贴片电阻; ID: 413; DSC2: 1/16W; DSC1: ±1%; ERP Number: 1010020064; PCB Footprint: R0402
footprint R0402
pins: 1, 2

## R-0402_Dup1_4
designator R?, comment 0R  PCB Footprint: R0402
Part Name: 贴片电阻; Part Number: C011002080413; ERP Number: 1010020064; DSC1: ±1%; DSC2: 1/16W; ID: 413
footprint R0402
pins: 1, 2

## R-0402_Dup1_5
designator R?, comment 10K
Part Name: 贴片电阻; Part Number: C011002080856; ERP Number: 1010020044; DSC1: ±1%; DSC2: 1/16W; ID: 856; PCB Footprint: R0402
footprint R0402
pins: 1, 2

## R-0402_Dup1_6
designator R?, comment NC/100K
Part Number: C011002080976; Part Name: 贴片电阻; ID: 976; DSC2: 1/16W; DSC1: ±1%; ERP Number: 1010020005; PCB Footprint: R0402
footprint R0402
pins: 1, 2

## R-0402_Dup1_7
designator R?, comment 100K
Part Name: 贴片电阻; Part Number: C011002080976; ERP Number: 1010020005; DSC1: ±1%; DSC2: 1/16W; ID: 976; PCB Footprint: R0402
footprint R0402
pins: 1, 2

## R-0402_Dup1_8
designator R?, comment NC/680R
Part Number: C011002080723; Part Name: 贴片电阻; ID: 723; DSC2: 1/16W; DSC1: ±1%; ERP Number: 1010020035; PCB Footprint: R0402
footprint R0402
pins: 1, 2

## R-0402_Dup3
designator R?, comment 3.3K
Part Number: C011002080799; Part Name: 贴片电阻; PCB Footprint: R0402; ID: 799; DSC2: 1/16W; DSC1: ±1%; ERP Number: 1010020209
footprint R0402
pins: 1, 2

## R-0402_Dup3_1
designator R?, comment 10K
Part Name: 贴片电阻; Part Number: C011002080856; PCB Footprint: R0402; ERP Number: 1010020044; DSC1: ±1%; DSC2: 1/16W; ID: 856
footprint R0402
pins: 1, 2

## R-0402_Dup3_2
designator R?, comment 15K
Part Name: 贴片电阻; Part Number: C011002080875; PCB Footprint: R0402; ERP Number: 1010020054; DSC1: ±1%; DSC2: 1/16W; ID: 875
footprint R0402
pins: 1, 2

## R-0402_Dup3_3
designator R?, comment 2.2K
Part Number: C011002080778; Part Name: 贴片电阻; PCB Footprint: R0402; ID: 778; DSC2: 1/16W; DSC1: ±1%; ERP Number: 1010020069
footprint R0402
pins: 1, 2

## R-0402_Dup3_4
designator R?, comment NC/75K
Part Number: C011002080961; Part Name: 贴片电阻; ID: 961; DSC2: 1/16W; DSC1: ±1%; ERP Number: 1010020058; PCB Footprint: R0402
footprint R0402
pins: 1, 2

## R-0402_Dup3_5
designator R?, comment 75K
Part Number: C011002080961; Part Name: 贴片电阻; ID: 961; DSC2: 1/16W; DSC1: ±1%; ERP Number: 1010020058; PCB Footprint: R0402
footprint R0402
pins: 1, 2

## R-0402_Dup3_6
designator R?, comment 0R
Part Number: C011002080413; Part Name: 贴片电阻; ID: 413; DSC2: 1/16W; DSC1: ±1%; ERP Number: 1010020064; PCB Footprint: R0402
footprint R0402
pins: 1, 2

## R-0402_Dup3_7
designator R?, comment 1K
Part Name: 贴片电阻; Part Number: C011002080742; ERP Number: 1010020016; DSC1: ±1%; DSC2: 1/16W; ID: 742; PCB Footprint: R0402
footprint R0402
pins: 1, 2

## R-0402_Dup4
designator R?, comment 100K
Part Number: C011002080353; Part Name: 贴片电阻; ID: 353; DSC2: 1/16W; DSC1: ±5%; ERP Number: 1010200103; PCB Footprint: R0402
footprint R0402
pins: 1, 2

## R-0402_Dup4_1
designator R?, comment 6.8K
Part Name: 贴片电阻; Part Number: C011002080324; PCB Footprint: R0402; DSC1: ±5%; DSC2: 1/16W; ID: 324
footprint R0402
pins: 1, 2

## R-0402_Dup5
designator R?, comment 200K
Part Name: 贴片电阻; Part Number: C011002080413; ERP Number: 1010020064; DSC1: ±1%; DSC2: 1/16W; ID: 413; PCB Footprint: R0402
footprint R0402
pins: 1, 2

## R-0402_Dup5_1
designator R?, comment 47K
Part Name: 贴片电阻; Part Number: C011002080345; ERP Number: 1010200182; DSC1: ±5%; DSC2: 1/16W; ID: 345; PCB Footprint: R0402
footprint R0402
pins: 1, 2

## R-0402_Dup5_2
designator R?, comment 54.9K 1%
Part Name: 贴片电阻; Part Number: C011002080978; ERP Number: 1010020226; DSC2: 1/16W; ID: 978; PCB Footprint: R0402
footprint R0402
pins: 1, 2

## R-0402_Dup5_3
designator R?, comment 10K 1%
Part Name: 贴片电阻; Part Number: C011002080889; ERP Number: 1010020122; DSC2: 1/16W; ID: 889; PCB Footprint: R0402
footprint R0402
pins: 1, 2

## R-0402_Dup5_4
designator R?, comment 33.2K
Part Name: 贴片电阻; Part Number: C011002080345; ERP Number: 1010200182; DSC1: ±5%; DSC2: 1/16W; ID: 345; PCB Footprint: R0402
footprint R0402
pins: 1, 2

## R-0402_Dup5_5
designator R?, comment 100R
Part Name: 贴片电阻; Part Number: C011002080279; ERP Number: 1010200160; DSC1: ±5%; DSC2: 1/16W; ID: 279; PCB Footprint: R0402
footprint R0402
pins: 1, 2

## R-0402_Dup5_6
designator R?, comment 22R
Part Name: 贴片电阻; Part Number: C011002080262; PCB Footprint: R0402; ERP Number: 1010200173; DSC1: ±5%; DSC2: 1/16W; ID: 262
footprint R0402
pins: 1, 2

## R-0402_Dup5_7
designator R?, comment 4.7K
Part Name: 贴片电阻; Part Number: C011002080320; PCB Footprint: R0402; ERP Number: 1010200177; DSC1: ±5%; DSC2: 1/16W; ID: 320
footprint R0402
pins: 1, 2

## R-0402_Dup5_8
designator R?, comment 2.2R
Part Name: 贴片电阻; Part Number: C011002080238; ERP Number: 1010200263; DSC1: ±5%; DSC2: 1/16W; ID: 238; PCB Footprint: R0402
footprint R0402
pins: 1, 2

## R-0402_Dup5_9
designator R?, comment 0R
Part Name: 贴片电阻; Part Number: C011002080217; ERP Number: 1010200100; DSC1: ±5%; DSC2: 1/16W; ID: 217; PCB Footprint: R0402
footprint R0402
pins: 1, 2

## R-0402_Dup5_10
designator R?, comment NC/0R
Part Number: C011002080217; Part Name: 贴片电阻; ID: 217; DSC2: 1/16W; DSC1: ±5%; ERP Number: 1010200100; PCB Footprint: R0402
footprint R0402
pins: 1, 2

## R-0402_Dup5_11
designator R?, comment NC/10K
Part Name: 贴片电阻; Part Number: C011002080856; ERP Number: 1010020044; DSC1: ±1%; DSC2: 1/16W; ID: 856; PCB Footprint: R0402
footprint R0402
pins: 1, 2

## R-0402_Dup5_12
designator R?, comment 4.7R
Part Number: C011002080246; Part Name: 贴片电阻; PCB Footprint: R0402; ID: 246; DSC2: 1/16W; DSC1: ±5%
footprint R0402
pins: 1, 2

## R-0402_Dup6
designator R?, comment 22R
Part Number: C011002080552; Part Name: 贴片电阻; PCB Footprint: R0402; ID: 552; DSC2: 1/16W; DSC1: ±1%; ERP Number: 1010020061
footprint R0402
pins: 1, 2

## R-0402_Dup6_1
designator R?, comment 0R
Part Name: 贴片电阻; Part Number: C011002080413; ERP Number: 1010020064; DSC1: ±1%; DSC2: 1/16W; ID: 413; PCB Footprint: R0402
footprint R0402
pins: 1, 2

## R-0402_Dup6_2
designator R?, comment 220K
Part Number: C011002081013; Part Name: 贴片电阻; PCB Footprint: R0402; ID: 1,013; DSC2: 1/16W; DSC1: ±1%; ERP Number: 1010020006
footprint R0402
pins: 1, 2

## R-0402_Dup6_3
designator R?, comment 100K
Part Name: 贴片电阻; Part Number: C011002080976; PCB Footprint: R0402; ERP Number: 1010020005; DSC1: ±1%; DSC2: 1/16W; ID: 976
footprint R0402
pins: 1, 2

## R-0402_Dup6_4
designator R?, comment 15K
Part Name: 贴片电阻; Part Number: C011002080875; PCB Footprint: R0402; ERP Number: 1010020054; DSC1: ±1%; DSC2: 1/16W; ID: 875
footprint R0402
pins: 1, 2

## R-0402_Dup6_5
designator R?, comment 33K
Part Number: C011002080914; Part Name: 贴片电阻; PCB Footprint: R0402; ID: 914; DSC2: 1/16W; DSC1: ±1%; ERP Number: 1010020124
footprint R0402
pins: 1, 2

## R-0402_Dup6_6
designator R?, comment 2.2R
Part Number: C011002080453; Part Name: 贴片电阻; ID: 453; DSC2: 1/16W; DSC1: ±1%; ERP Number: 1010020066; PCB Footprint: R0402
footprint R0402
pins: 1, 2

## R-0402_Dup6_7
designator R?, comment 1.1K
Part Name: 贴片电阻; Part Number: C011002080746; ERP Number: 1010020236; DSC1: ±1%; DSC2: 1/16W; ID: 746; PCB Footprint: R0402
footprint R0402
pins: 1, 2

## R-0402_Dup6_8
designator R?, comment 10K
Part Number: C011002080856; Part Name: 贴片电阻; PCB Footprint: R0402; ID: 856; DSC2: 1/16W; DSC1: ±1%; ERP Number: 1010020044
footprint R0402
pins: 1, 2

## R-0402_Dup7
designator R?, comment 1K
Part Number: C011002080742; Part Name: 贴片电阻; ID: 742; DSC2: 1/16W; DSC1: ±1%; ERP Number: 1010020016; PCB Footprint: R0402
footprint R0402
pins: 1, 2

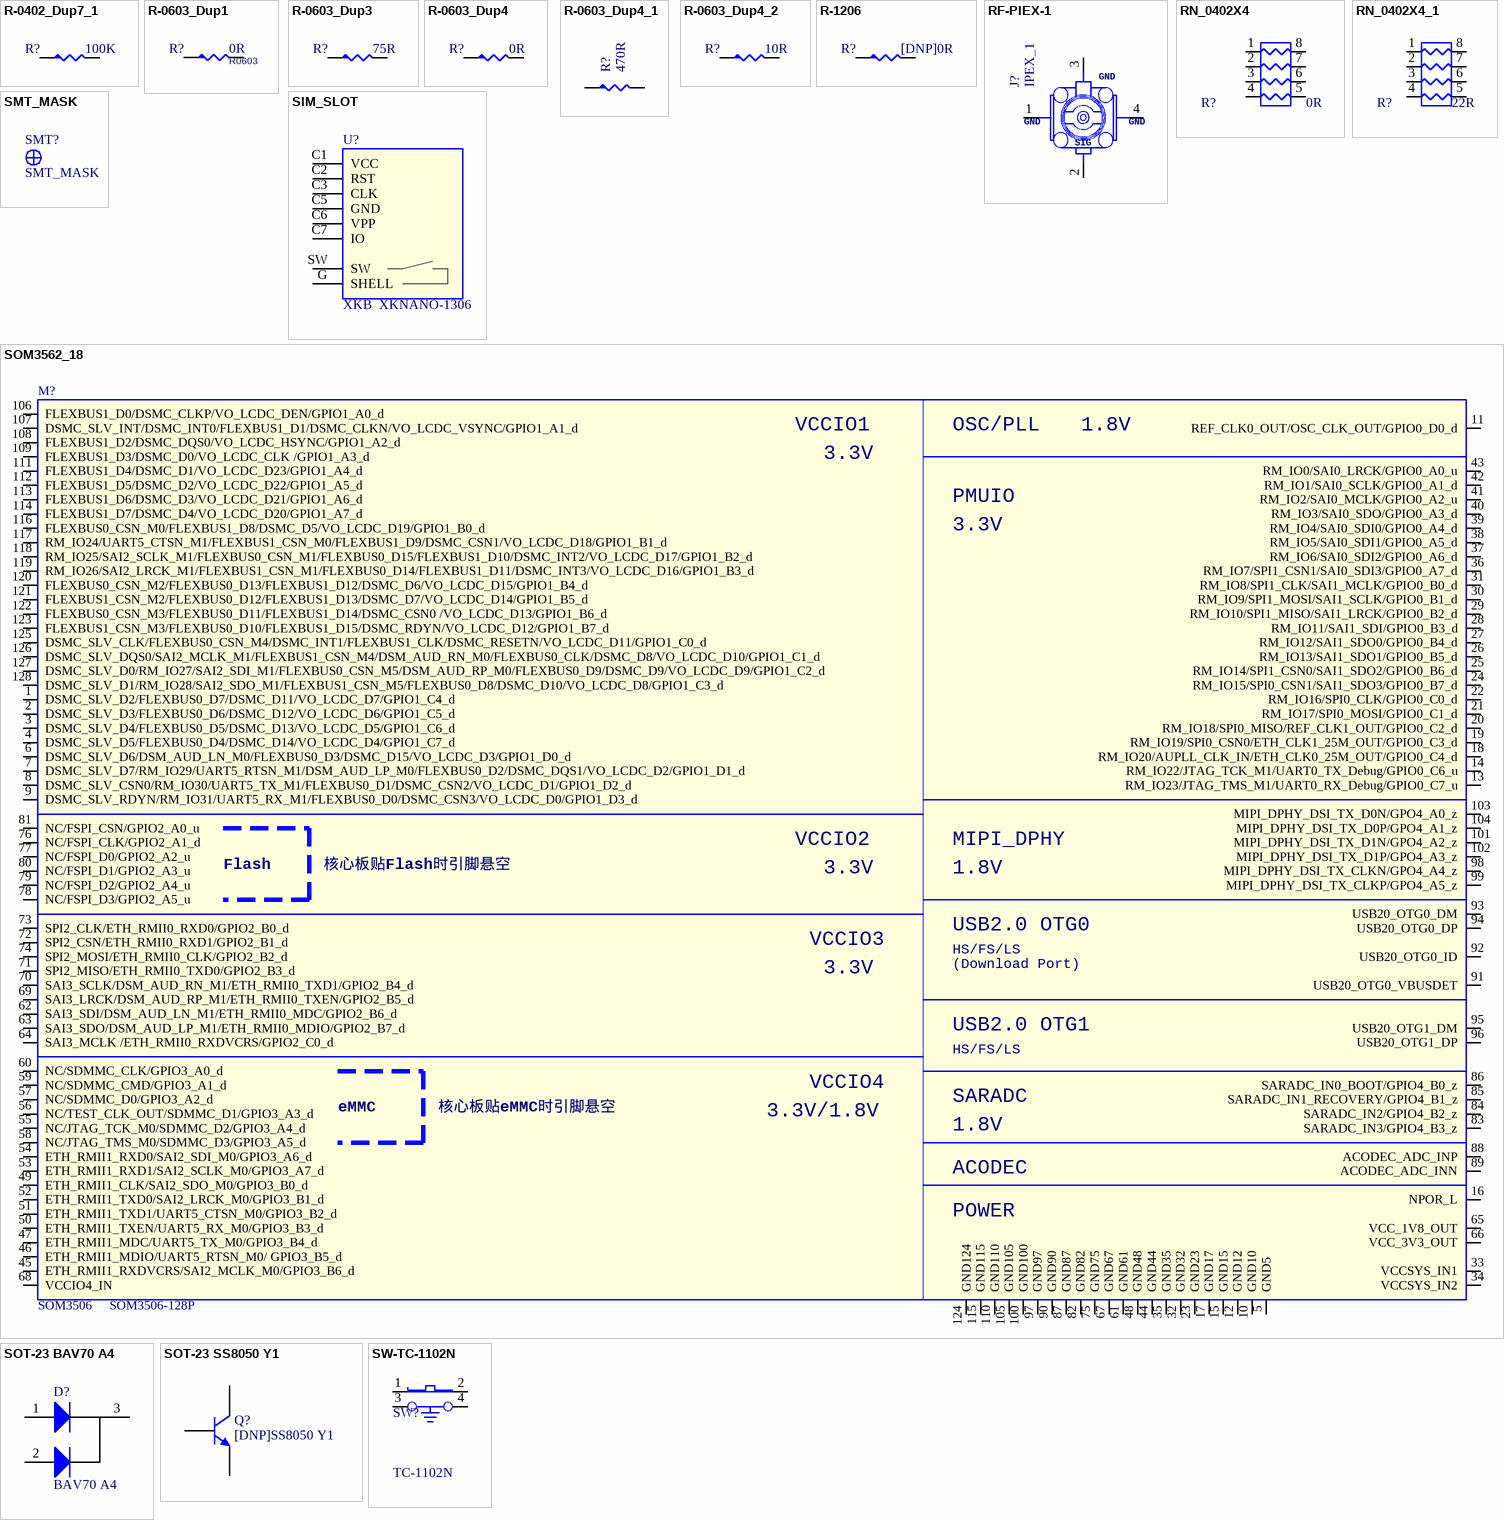
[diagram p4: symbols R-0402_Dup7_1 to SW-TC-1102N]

## R-0402_Dup7_1
designator R?, comment 100K
Part Name: 贴片电阻; Part Number: C011002080976; PCB Footprint: R0402; ERP Number: 1010020005; DSC1: ±1%; DSC2: 1/16W; ID: 976
footprint R0402
pins: 1, 2

## R-0603_Dup1
designator R?, comment 0R  PCB Footprint: R0603
Part Number: C011002081182; Part Name: 贴片电阻; ID: 1,182; DSC2: 1/10W; DSC1: ±1%; ERP Number: 1010020084
footprint R0603
pins: 1, 2

## R-0603_Dup3
designator R?, comment 75R
Part Name: 贴片电阻; Part Number: C011002081348; PCB Footprint: R0603; ERP Number: 1010200269; DSC1: ±1%; DSC2: 1/10W; ID: 1,348
footprint R0603
pins: 1, 2

## R-0603_Dup4
designator R?, comment 0R
Part Name: 贴片电阻; Part Number: C011002081182; PCB Footprint: R0603; ERP Number: 1010020084; DSC1: ±1%; DSC2: 1/10W; ID: 1,182
footprint R0603
pins: 1, 2

## R-0603_Dup4_1
designator R?, comment 470R
Part Number: C011002081396; Part Name: 贴片电阻; PCB Footprint: R0603; ID: 1,396; DSC2: 1/10W; DSC1: ±1%; ERP Number: 1010020278
footprint R0603
pins: 1, 2

## R-0603_Dup4_2
designator R?, comment 10R
Part Name: 贴片电阻; Part Number: C011002081261; PCB Footprint: R0603; ERP Number: 1010020028; DSC1: ±1%; DSC2: 1/10W; ID: 1,261
footprint R0603
pins: 1, 2

## R-1206
designator R?, comment [DNP]0R
Part Name: 贴片电阻; Part Number: C011002081877; ERP Number: 1010200214; DSC1: ±1%; DSC2: 1/4W; ID: 1,877; PCB Footprint: R1206
footprint R1206
pins: 1, 2

## RF-PIEX-1
designator J?, comment IPEX_1
SMD micro Coaxial Connector Receptacle vertial; Part Number: J110103040001; Part Name: IPEX-1代; Pack_Type: MHF-20279; ERP Number: 1030100002; DSC1: 射频同轴一代IPEX板端贴片天线座子 IPEX-1代 SMD 内针; DSC2: 贴片; DSC3: U.FL-R-SMT-1(80) 广濑; DSC4: KH-IPEX-K501-29(金航标); ID: 1; PCB Footprint: IPEX-001E
footprint IPEX-001E
pins: 1 GND1, 2 SIG, 3 GND2, 4 GND3

## RN_0402X4
designator R?, comment 0R
Part Name: 贴片排阻; Part Number: C010302090001; PCB Footprint: RN_0402X4; ID: 1; ERP Number: 1010020101; DSC1: ±5%; DSC2: 1/16W
footprint RN_0402X4
pins: 1, 2, 3, 4, 5, 6, 7, 8

## RN_0402X4_1
designator R?, comment 22R
Part Name: 贴片排阻; Part Number: C010302090004; ID: 4; ERP Number: 1010020076; DSC1: ±5%; DSC2: 1/16W; PCB Footprint: RN_0402X4
footprint RN_0402X4
pins: 1, 2, 3, 4, 5, 6, 7, 8

## SIM_SLOT
designator U?, comment XKB  XKNANO-1306
footprint nano_sim_6p_flip_type
pins: C1 VCC, C2 RST, C3 CLK, C5 GND, C6 VPP, C7 IO, G SHELL, SW

## SMT_MASK
designator SMT?
SMT_MASK for SMD manufacture
footprint SMT_MARK
pins: 1

## SOM3562_18
designator M?, comment SOM3506  PCB Footprint: SOM3506-128P
footprint SOM3506-128P
footprint SOM3506-128P
pins: 1 DSMC_SLV_D2/FLEXBUS0_D7/DSMC_D11/VO_LCDC_D7/GPIO1_C4_d, 2 DSMC_SLV_D3/FLEXBUS0_D6/DSMC_D12/VO_LCDC_D6/GPIO1_C5_d, 3 DSMC_SLV_D4/FLEXBUS0_D5/DSMC_D13/VO_LCDC_D5/GPIO1_C6_d, 4 DSMC_SLV_D5/FLEXBUS0_D4/DSMC_D14/VO_LCDC_D4/GPIO1_C7_d, 5 GND5, 6 DSMC_SLV_D6/DSM_AUD_LN_M0/FLEXBUS0_D3/DSMC_D15/VO_LCDC_D3/GPIO1_D0_d, 7 DSMC_SLV_D7/RM_IO29/UART5_RTSN_M1/DSM_AUD_LP_M0/FLEXBUS0_D2/DSMC_DQS1/VO_LCDC_D2/GPIO1_D1_d, 8 DSMC_SLV_CSN0/RM_IO30/UART5_TX_M1/FLEXBUS0_D1/DSMC_CSN2/VO_LCDC_D1/GPIO1_D2_d, 9 DSMC_SLV_RDYN/RM_IO31/UART5_RX_M1/FLEXBUS0_D0/DSMC_CSN3/VO_LCDC_D0/GPIO1_D3_d, 10 GND10, 11 REF_CLK0_OUT/OSC_CLK_OUT/GPIO0_D0_d, 12 GND12, 13 RM_IO23/JTAG_TMS_M1/UART0_RX_Debug/GPIO0_C7_u, 14 RM_IO22/JTAG_TCK_M1/UART0_TX_Debug/GPIO0_C6_u, 15 GND15, 16 NPOR_L, 17 GND17, 18 RM_IO20/AUPLL_CLK_IN/ETH_CLK0_25M_OUT/GPIO0_C4_d, 19 RM_IO19/SPI0_CSN0/ETH_CLK1_25M_OUT/GPIO0_C3_d, 20 RM_IO18/SPI0_MISO/REF_CLK1_OUT/GPIO0_C2_d, 21 RM_IO17/SPI0_MOSI/GPIO0_C1_d, 22 RM_IO16/SPI0_CLK/GPIO0_C0_d, 23 GND23, 24 RM_IO15/SPI0_CSN1/SAI1_SDO3/GPIO0_B7_d, 25 RM_IO14/SPI1_CSN0/SAI1_SDO2/GPIO0_B6_d, 26 RM_IO13/SAI1_SDO1/GPIO0_B5_d, 27 RM_IO12/SAI1_SDO0/GPIO0_B4_d, 28 RM_IO11/SAI1_SDI/GPIO0_B3_d, 29 RM_IO10/SPI1_MISO/SAI1_LRCK/GPIO0_B2_d, 30 RM_IO9/SPI1_MOSI/SAI1_SCLK/GPIO0_B1_d, 31 RM_IO8/SPI1_CLK/SAI1_MCLK/GPIO0_B0_d, 32 GND32, 33 VCCSYS_IN1, 34 VCCSYS_IN2, 35 GND35, 36 RM_IO7/SPI1_CSN1/SAI0_SDI3/GPIO0_A7_d, 37 RM_IO6/SAI0_SDI2/GPIO0_A6_d, 38 RM_IO5/SAI0_SDI1/GPIO0_A5_d, 39 RM_IO4/SAI0_SDI0/GPIO0_A4_d, 40 RM_IO3/SAI0_SDO/GPIO0_A3_d, 41 RM_IO2/SAI0_MCLK/GPIO0_A2_u, 42 RM_IO1/SAI0_SCLK/GPIO0_A1_d, 43 RM_IO0/SAI0_LRCK/GPIO0_A0_u, 44 GND44, 45 ETH_RMII1_RXDVCRS/SAI2_MCLK_M0/GPIO3_B6_d, 46 ETH_RMII1_MDIO/UART5_RTSN_M0/ GPIO3_B5_d, 47 ETH_RMII1_MDC/UART5_TX_M0/GPIO3_B4_d, 48 GND48, 49 ETH_RMII1_CLK/SAI2_SDO_M0/GPIO3_B0_d, 50 ETH_RMII1_TXEN/UART5_RX_M0/GPIO3_B3_d, 51 ETH_RMII1_TXD1/UART5_CTSN_M0/GPIO3_B2_d, 52 ETH_RMII1_TXD0/SAI2_LRCK_M0/GPIO3_B1_d, 53 ETH_RMII1_RXD1/SAI2_SCLK_M0/GPIO3_A7_d, 54 ETH_RMII1_RXD0/SAI2_SDI_M0/GPIO3_A6_d, 55 NC/JTAG_TCK_M0/SDMMC_D2/GPIO3_A4_d, 56 NC/TEST_CLK_OUT/SDMMC_D1/GPIO3_A3_d, 57 NC/SDMMC_D0/GPIO3_A2_d, 58 NC/JTAG_TMS_M0/SDMMC_D3/GPIO3_A5_d, 59 NC/SDMMC_CMD/GPIO3_A1_d, 60 NC/SDMMC_CLK/GPIO3_A0_d, 61 GND61, 62 SAI3_SDI/DSM_AUD_LN_M1/ETH_RMII0_MDC/GPIO2_B6_d, 63 SAI3_SDO/DSM_AUD_LP_M1/ETH_RMII0_MDIO/GPIO2_B7_d, 64 SAI3_MCLK /ETH_RMII0_RXDVCRS/GPIO2_C0_d, 65 VCC_1V8_OUT, 66 VCC_3V3_OUT, 67 GND67, 68 VCCIO4_IN, 69 SAI3_LRCK/DSM_AUD_RP_M1/ETH_RMII0_TXEN/GPIO2_B5_d, 70 SAI3_SCLK/DSM_AUD_RN_M1/ETH_RMII0_TXD1/GPIO2_B4_d, 71 SPI2_MISO/ETH_RMII0_TXD0/GPIO2_B3_d, 72 SPI2_CSN/ETH_RMII0_RXD1/GPIO2_B1_d, 73 SPI2_CLK/ETH_RMII0_RXD0/GPIO2_B0_d, 74 SPI2_MOSI/ETH_RMII0_CLK/GPIO2_B2_d, 75 GND75, 76 NC/FSPI_CLK/GPIO2_A1_d, 77 NC/FSPI_D0/GPIO2_A2_u, 78 NC/FSPI_D3/GPIO2_A5_u, 79 NC/FSPI_D2/GPIO2_A4_u, 80 NC/FSPI_D1/GPIO2_A3_u, 81 NC/FSPI_CSN/GPIO2_A0_u, 82 GND82, 83 SARADC_IN3/GPIO4_B3_z, 84 SARADC_IN2/GPIO4_B2_z, 85 SARADC_IN1_RECOVERY/GPIO4_B1_z, 86 SARADC_IN0_BOOT/GPIO4_B0_z, 87 GND87, 88 ACODEC_ADC_INP, 89 ACODEC_ADC_INN, 90 GND90, 91 USB20_OTG0_VBUSDET, 92 USB20_OTG0_ID, 93 USB20_OTG0_DM, 94 USB20_OTG0_DP, 95 USB20_OTG1_DM, 96 USB20_OTG1_DP, 97 GND97, 98 MIPI_DPHY_DSI_TX_CLKN/GPO4_A4_z, 99 MIPI_DPHY_DSI_TX_CLKP/GPO4_A5_z, 100 GND100, 101 MIPI_DPHY_DSI_TX_D1N/GPO4_A2_z, 102 MIPI_DPHY_DSI_TX_D1P/GPO4_A3_z, 103 MIPI_DPHY_DSI_TX_D0N/GPO4_A0_z, 104 MIPI_DPHY_DSI_TX_D0P/GPO4_A1_z, 105 GND105, 106 FLEXBUS1_D0/DSMC_CLKP/VO_LCDC_DEN/GPIO1_A0_d, 107 DSMC_SLV_INT/DSMC_INT0/FLEXBUS1_D1/DSMC_CLKN/VO_LCDC_VSYNC/GPIO1_A1_d, 108 FLEXBUS1_D2/DSMC_DQS0/VO_LCDC_HSYNC/GPIO1_A2_d, 109 FLEXBUS1_D3/DSMC_D0/VO_LCDC_CLK /GPIO1_A3_d, 110 GND110, 111 FLEXBUS1_D4/DSMC_D1/VO_LCDC_D23/GPIO1_A4_d, 112 FLEXBUS1_D5/DSMC_D2/VO_LCDC_D22/GPIO1_A5_d, 113 FLEXBUS1_D6/DSMC_D3/VO_LCDC_D21/GPIO1_A6_d, 114 FLEXBUS1_D7/DSMC_D4/VO_LCDC_D20/GPIO1_A7_d, 115 GND115, 116 FLEXBUS0_CSN_M0/FLEXBUS1_D8/DSMC_D5/VO_LCDC_D19/GPIO1_B0_d, 117 RM_IO24/UART5_CTSN_M1/FLEXBUS1_CSN_M0/FLEXBUS1_D9/DSMC_CSN1/VO_LCDC_D18/GPIO1_B1_d, 118 RM_IO25/SAI2_SCLK_M1/FLEXBUS0_CSN_M1/FLEXBUS0_D15/FLEXBUS1_D10/DSMC_INT2/VO_LCDC_D17/GPIO1_B2_d, 119 RM_IO26/SAI2_LRCK_M1/FLEXBUS1_CSN_M1/FLEXBUS0_D14/FLEXBUS1_D11/DSMC_INT3/VO_LCDC_D16/GPIO1_B3_d, 120 FLEXBUS0_CSN_M2/FLEXBUS0_D13/FLEXBUS1_D12/DSMC_D6/VO_LCDC_D15/GPIO1_B4_d, 121 FLEXBUS1_CSN_M2/FLEXBUS0_D12/FLEXBUS1_D13/DSMC_D7/VO_LCDC_D14/GPIO1_B5_d, 122 FLEXBUS0_CSN_M3/FLEXBUS0_D11/FLEXBUS1_D14/DSMC_CSN0 /VO_LCDC_D13/GPIO1_B6_d, 123 FLEXBUS1_CSN_M3/FLEXBUS0_D10/FLEXBUS1_D15/DSMC_RDYN/VO_LCDC_D12/GPIO1_B7_d, 124 GND124, 125 DSMC_SLV_CLK/FLEXBUS0_CSN_M4/DSMC_INT1/FLEXBUS1_CLK/DSMC_RESETN/VO_LCDC_D11/GPIO1_C0_d, 126 DSMC_SLV_DQS0/SAI2_MCLK_M1/FLEXBUS1_CSN_M4/DSM_AUD_RN_M0/FLEXBUS0_CLK/DSMC_D8/VO_LCDC_D10/GPIO1_C1_d, 127 DSMC_SLV_D0/RM_IO27/SAI2_SDI_M1/FLEXBUS0_CSN_M5/DSM_AUD_RP_M0/FLEXBUS0_D9/DSMC_D9/VO_LCDC_D9/GPIO1_C2_d, 128 DSMC_SLV_D1/RM_IO28/SAI2_SDO_M1/FLEXBUS1_CSN_M5/FLEXBUS0_D8/DSMC_D10/VO_LCDC_D8/GPIO1_C3_d

## SOT-23 BAV70 A4
designator D?, comment BAV70 A4
开关二极管
footprint SOT-23-3 (http://www.aosmd.com/res/packaging_information/SOT-23-3L.pdf)
pins: 1 A, 2 A, 3 K

## SOT-23 SS8050 Y1
designator Q?, comment [DNP]SS8050 Y1
三极管
footprint SOT-23-3 (http://www.aosmd.com/res/packaging_information/SOT-23-3L.pdf)
pins: 1 B, 2 E, 3 C

## SW-TC-1102N
designator SW?, comment TC-1102N
TC-1102N 直插轻触开关; PCB Footprint: PB-SIDE-S-3_5x4_5
footprint SW-SMD_GT-TC108A-H034-L1S
pins: 1, 2, 3, 4

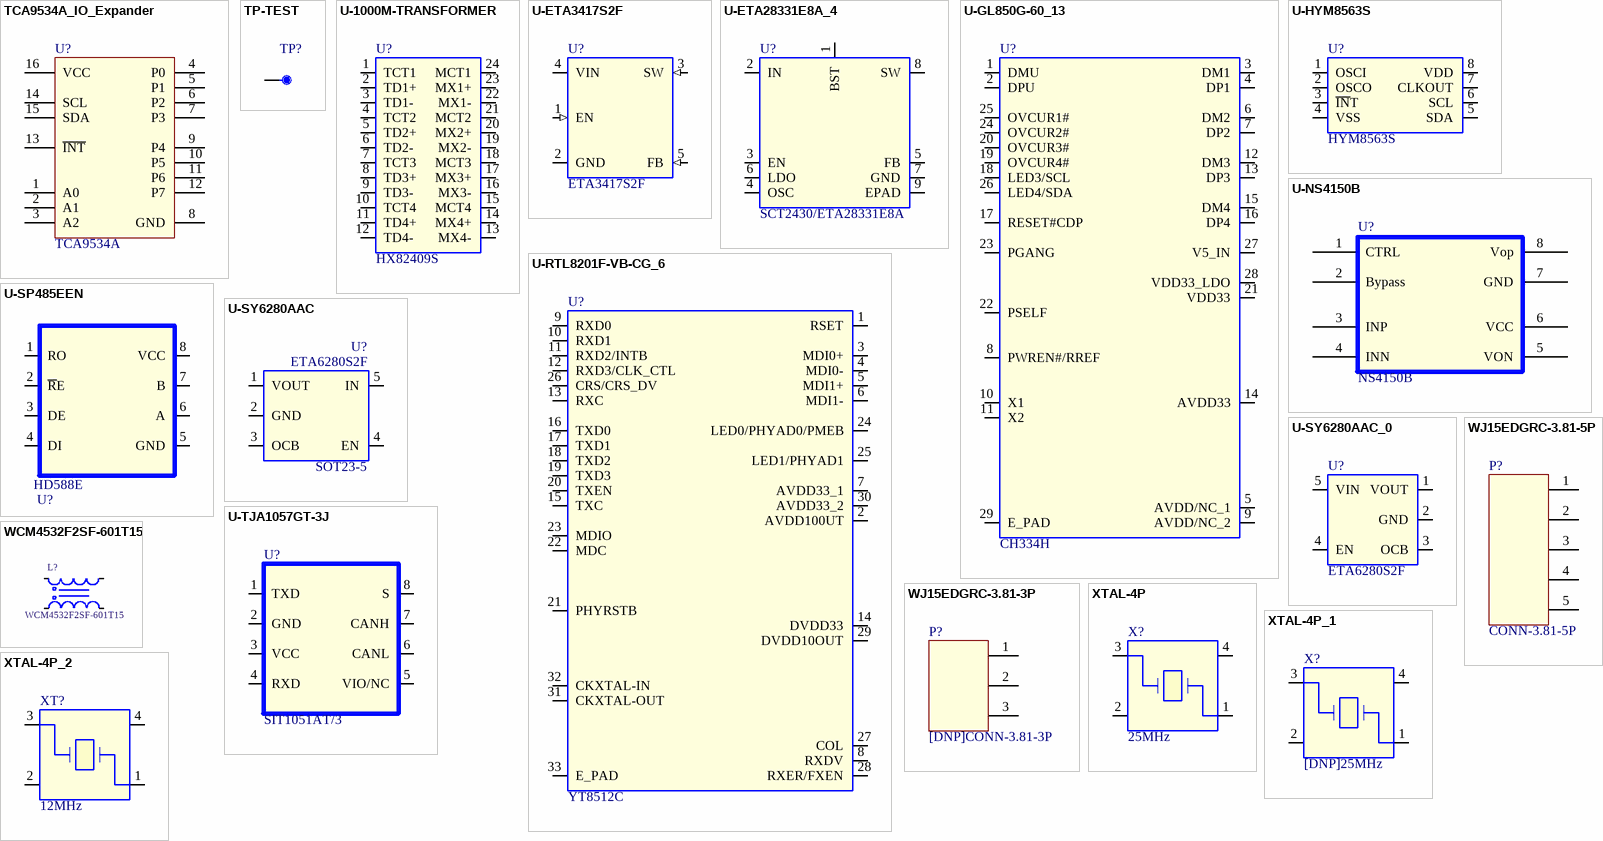
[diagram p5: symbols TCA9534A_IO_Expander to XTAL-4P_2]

## TCA9534A_IO_Expander
designator U?, comment TCA9534A
TCA9534A I2C to 8bit paralla IO expander.
footprint TSSOP-16_L5.0-W4.4-P0.65-LS6.4-BL
pins: 1 A0, 2 A1, 3 A2, 4 P0, 5 P1, 6 P2, 7 P3, 8 GND, 9 P4, 10 P5, 11 P6, 12 P7, 13 ~{INT}, 14 SCL, 15 SDA, 16 VCC

## TP-TEST
designator TP?, comment TP100  (value not drawn)
Part Number: CAD; Part Name: 测试点; DSC1: 焊盘1mm; DSC2: 无孔; DSC3: 圆形; DSC4: 单面; ID: 3
footprint TP100
pins: 1

## U-1000M-TRANSFORMER
designator U?, comment HX82409S
Manufacture: Hqst(盈盛电子); Part Name: 网口变压器; DSC3: SMD,SOP24,15.1*7.1*4mm; DSC2: -40℃~+85℃; DSC1: 贴片 单口千兆或双口百兆,支持POE; ERP Number: 1010030021; ID: 3; PCB Footprint: SMD24-P100-710X1510
footprint SMD24-P100-710X1510
pins: 1 TCT1, 2 TD1+, 3 TD1-, 4 TCT2, 5 TD2+, 6 TD2-, 7 TCT3, 8 TD3+, 9 TD3-, 10 TCT4, 11 TD4+, 12 TD4-, 13 MX4-, 14 MX4+, 15 MCT4, 16 MX3-, 17 MX3+, 18 MCT3, 19 MX2-, 20 MX2+, 21 MCT2, 22 MX1-, 23 MX1+, 24 MCT1

## U-ETA3417S2F
designator U?, comment ETA3417S2F
Manufacture: ETA(钰泰); Part Number: C070205183984; Part Name: DCDC; ID: 43; Solder: 量产; DSC7: 同步降压; DSC6: 3MHz; DSC5: 0.96; DSC4: Vfb=0.6V; DSC3: Io=2.5A; DSC2: Vo=0.6-7V; DSC1: Vi=2.6-7.0V; ERP Number: 1020040087; PCB Footprint: SOT23-5
footprint SOT23-5
pins: 1 EN (in), 2 GND (power), 3 SW (in), 4 VIN (power), 5 FB (in)

## U-ETA28331E8A_4
designator U?, comment SCT2430/ETA28331E8A
Manufacture: ETA(钰泰); Part Name: DCDC; ID: 63; Solder: 推荐; DSC7: 同步降压; DSC6: 0.12-1.1MHz; DSC5: 0.95; DSC4: Vfb=0.8V; DSC3: Io=4.5A; DSC2: Vo=0.8-35V; DSC1: Vi=4.6-35V; ERP Number: 1020030043; PCB Footprint: ESOP8-ETA28331E8A
footprint ESOP8-ETA28331E8A
pins: 1 BST, 2 IN, 3 EN, 4 OSC, 5 FB, 6 LDO, 7 GND, 8 SW, 9 EPAD

## U-GL850G-60_13
designator U?, comment CH334H
Manufacture: WCH(南京沁恒); Part Name: USB芯片; ID: 38; DSC3: -40℃~+85℃; DSC2: QFN28，5x5mm，0.5mm Pitch; DSC1: USB2.0 hub 4Ports; PCB Footprint: QFN-28_5x5x05P_CH334H
footprint QFN-28_5x5x05P_CH334H
pins: 1 DMU, 2 DPU, 3 DM1, 4 DP1, 5 AVDD/NC_1, 6 DM2, 7 DP2, 8 PWREN#/RREF, 9 AVDD/NC_2, 10 X1, 11 X2, 12 DM3, 13 DP3, 14 AVDD33, 15 DM4, 16 DP4, 17 RESET#CDP, 18 LED3/SCL, 19 OVCUR4#, 20 OVCUR3#, 21 VDD33, 22 PSELF, 23 PGANG, 24 OVCUR2#, 25 OVCUR1#, 26 LED4/SDA, 27 V5_IN, 28 VDD33_LDO, 29 E_PAD

## U-HYM8563S
designator U?, comment HYM8563S
Part Number: C110204273853; Part Name: RTC芯片; Manufacture: HAOYU(昊昱); PCB Footprint: MSOP-8; DSC1: RTC,I2C, VCC=2.0-5.5V; DSC2: TSSOP8; DSC3: -40℃~+85℃; ID: 16
footprint MSOP-8
pins: 1 OSCI, 2 OSCO, 3 ~{IN}T, 4 VSS, 5 SDA, 6 SCL, 7 CLKOUT, 8 VDD

## U-NS4150B
designator U?, comment NS4150B
Manufacture: Nsiway(纳芯威); Part Number: C150102670003; Part Name: 功放; PCB Footprint: MSOP-8; ID: 3; DSC3: -40~+85℃; DSC1: 1*3W @4Ω,Vin=3-5.2V,Class D; ERP Number: 1020040034
footprint MSOP-8
pins: 1 CTRL, 2 Bypass, 3 INP, 4 INN, 5 VON, 6 VCC, 7 GND, 8 Vop

## U-RTL8201F-VB-CG_6
designator U?, comment YT8512C
Part Number: C100102490008; Part Name: 以太网芯片; Manufacture: REALTEK(瑞昱); PCB Footprint: QFN-32_5x5x05P_RTL8201F-VB-CG; ERP Number: 1020040017; DSC1: 100M PHY芯片; DSC2: QFN32，5x5mm，0.5mm Pitch; DSC3: 0℃~+70℃; ID: 8
footprint QFN-32_5x5x05P_RTL8201F-VB-CG
pins: 1 RSET, 2 AVDD100UT, 3 MDI0+, 4 MDI0-, 5 MDI1+, 6 MDI1-, 7 AVDD33_1, 8 RXDV, 9 RXD0, 10 RXD1, 11 RXD2/INTB, 12 RXD3/CLK_CTL, 13 RXC, 14 DVDD33, 15 TXC, 16 TXD0, 17 TXD1, 18 TXD2, 19 TXD3, 20 TXEN, 21 PHYRSTB, 22 MDC, 23 MDIO, 24 LED0/PHYAD0/PMEB, 25 LED1/PHYAD1, 26 CRS/CRS_DV, 27 COL, 28 RXER/FXEN, 29 DVDD10OUT, 30 AVDD33_2, 31 CKXTAL-OUT, 32 CKXTAL-IN, 33 E_PAD

## U-SP485EEN
designator U?, comment HD588E
Part Number: C100305124695; Part Name: RS485芯片; Manufacture: Broadic(展恒电子); ERP Number: 1020040100; DSC1: RS485 Transceiver ,up to 1Mbps; DSC2: SOIC-8_150mil，1.27mm Pitch; DSC3: -40℃~+125℃; ID: 75; PCB Footprint: SOP8-P127-390X490
footprint SOP8-P127-390X490
pins: 1 RO, 2 ~{R}E, 3 DE, 4 DI, 5 GND, 6 A, 7 B, 8 VCC

## U-SY6280AAC
designator U?, comment ETA6280S2F  PCB Footprint: SOT23-5
Part Name: 功率开关; Manufacture: ETA; DSC1: 低能耗电源开关; DSC2: 2.4-5.5V 2A; DSC3: 80mA; DSC4: -40~85℃; ID: 1
footprint SOT23-5
pins: 1 VOUT, 2 GND, 3 OCB, 4 EN, 5 IN

## U-SY6280AAC_0
designator U?, comment ETA6280S2F
Manufacture: ETA(钰泰); Part Name: 功率开关; PCB Footprint: SOT23-5; ID: 6; DSC4: -40~+85℃; DSC3: Ron=70m?; DSC2: VIN=2.1-6V,ILIM=2.2A; DSC1: 低能耗电源开关; ERP Number: 1020030035
footprint SOT23-5
pins: 1 VOUT, 2 GND, 3 OCB, 4 EN, 5 VIN

## U-TJA1057GT-3J
designator U?, comment SIT1051AT/3
Part Name: CAN芯片; Manufacture: SIT(芯力特); ERP Number: 1020040202; DSC1: CAN Transceiver, 5Mbps; DSC2: SOIC-8_150mil，1.27mm Pitch; DSC3: -40℃~+85℃; ID: 92; PCB Footprint: SOP8-P127-390X490
footprint SOP8-P127-390X490
pins: 1 TXD, 2 GND, 3 VCC, 4 RXD, 5 VIO/NC, 6 CANL, 7 CANH, 8 S

## WCM4532F2SF-601T15
designator L?
Manufacturer: TAI-TECH(台庆); Add into BOM: yes; Number of Lines: 2; Current Rating: 1.5A; Voltage Rating - DC: 50V; Impedance @ Frequency: 600Ω@100MHz; DC Resistance (DCR): 240mΩ
footprint FILTER-SMD_4P-L4.5-W3.2-TL_ACT45B
3D model FILTER-SMD_4P-L4.5-W3.2-H2.6
pins: 1, 2, 3, 4

## WJ15EDGRC-3.81-3P
designator P?, comment [DNP]CONN-3.81-3P
footprint CONN-TH_3P-P3.81
pins: 1, 2, 3

## WJ15EDGRC-3.81-5P
designator P?, comment CONN-3.81-5P
footprint CONN-TH_5P-P3.81_WJ15EDGRC-3.81-5P - duplicate
pins: 1, 2, 3, 4, 5

## XTAL-4P
designator X?, comment 25MHz
Manufacture: TKD(泰晶); Part Number: C050102290006; Part Name: 贴片无源晶振; CLASS: IC; PCB Footprint: XTAL_32X25_4P; ID: 6; DSC5: 3.2*2.5mm 4P; DSC4: -40℃~+85℃; DSC3: 12pF; DSC2: ±10ppm; DSC1: ESR=40Ω; ERP Number: 1010090004
footprint XTAL_32X25_4P
pins: 1, 2, 3, 4

## XTAL-4P_1
designator X?, comment [DNP]25MHz
Manufacture: TKD(泰晶); Part Number: C050102290006; Part Name: 贴片无源晶振; CLASS: IC; PCB Footprint: XTAL_32X25_4P; ID: 6; DSC5: 3.2*2.5mm 4P; DSC4: -40℃~+85℃; DSC3: 12pF; DSC2: ±10ppm; DSC1: ESR=40Ω; ERP Number: 1010090004
footprint XTAL_32X25_4P
pins: 1, 2, 3, 4

## XTAL-4P_2
designator XT?, comment 12MHz
Part Name: 贴片无源晶振; Part Number: C050102290004; Manufacture: TKD(泰晶); CLASS: IC; ERP Number: 1010090003; DSC1: ESR=100Ω; DSC2: ±10ppm; DSC3: 12pF; DSC4: -40℃~+85℃; DSC5: 3.2*2.5mm 4P; ID: 4; PCB Footprint: XTAL_32X25_4P
footprint XTAL_32X25_4P
pins: 1, 2, 3, 4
